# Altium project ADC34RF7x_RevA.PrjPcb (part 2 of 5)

## Sheet ADC34RF7x_ADC_Power_RevA.SchDoc: ADC EVM Power
size 431 x 279 mm; Date: Not shown in title block; ApprovedBy: Not shown in title block; CheckedBy: Not shown in title block; Author: Not shown in title block; CompanyName: Not shown in title block; DrawnBy: CW; Engineer: Not shown in title block; Organization: Not shown in title block; Address1: Not shown in title block; Address2: Not shown in title block; Address3: Not shown in title block; Address4: Not shown in title block; DocumentNumber: 4; Revision: Use project parameter SCH_Rev; SheetNumber: 6; SheetTotal: 20; PageSetup: Record=PageOptions¦CenterHorizontal=True¦CenterVertical=True¦PrintScale=1.00¦XCorrection=1.00¦YCorrection=1.00¦PrintKind=0¦BorderSize=5000000¦LeftOffset=0¦BottomOffset=0¦Orientation=2¦PaperLength=1000¦PaperWidth=1000¦Scale=100¦PaperSource=15¦PrintQuality=600¦MediaType=1¦DitherType=10¦PaperKind=Letter¦PrintScaleMode=1
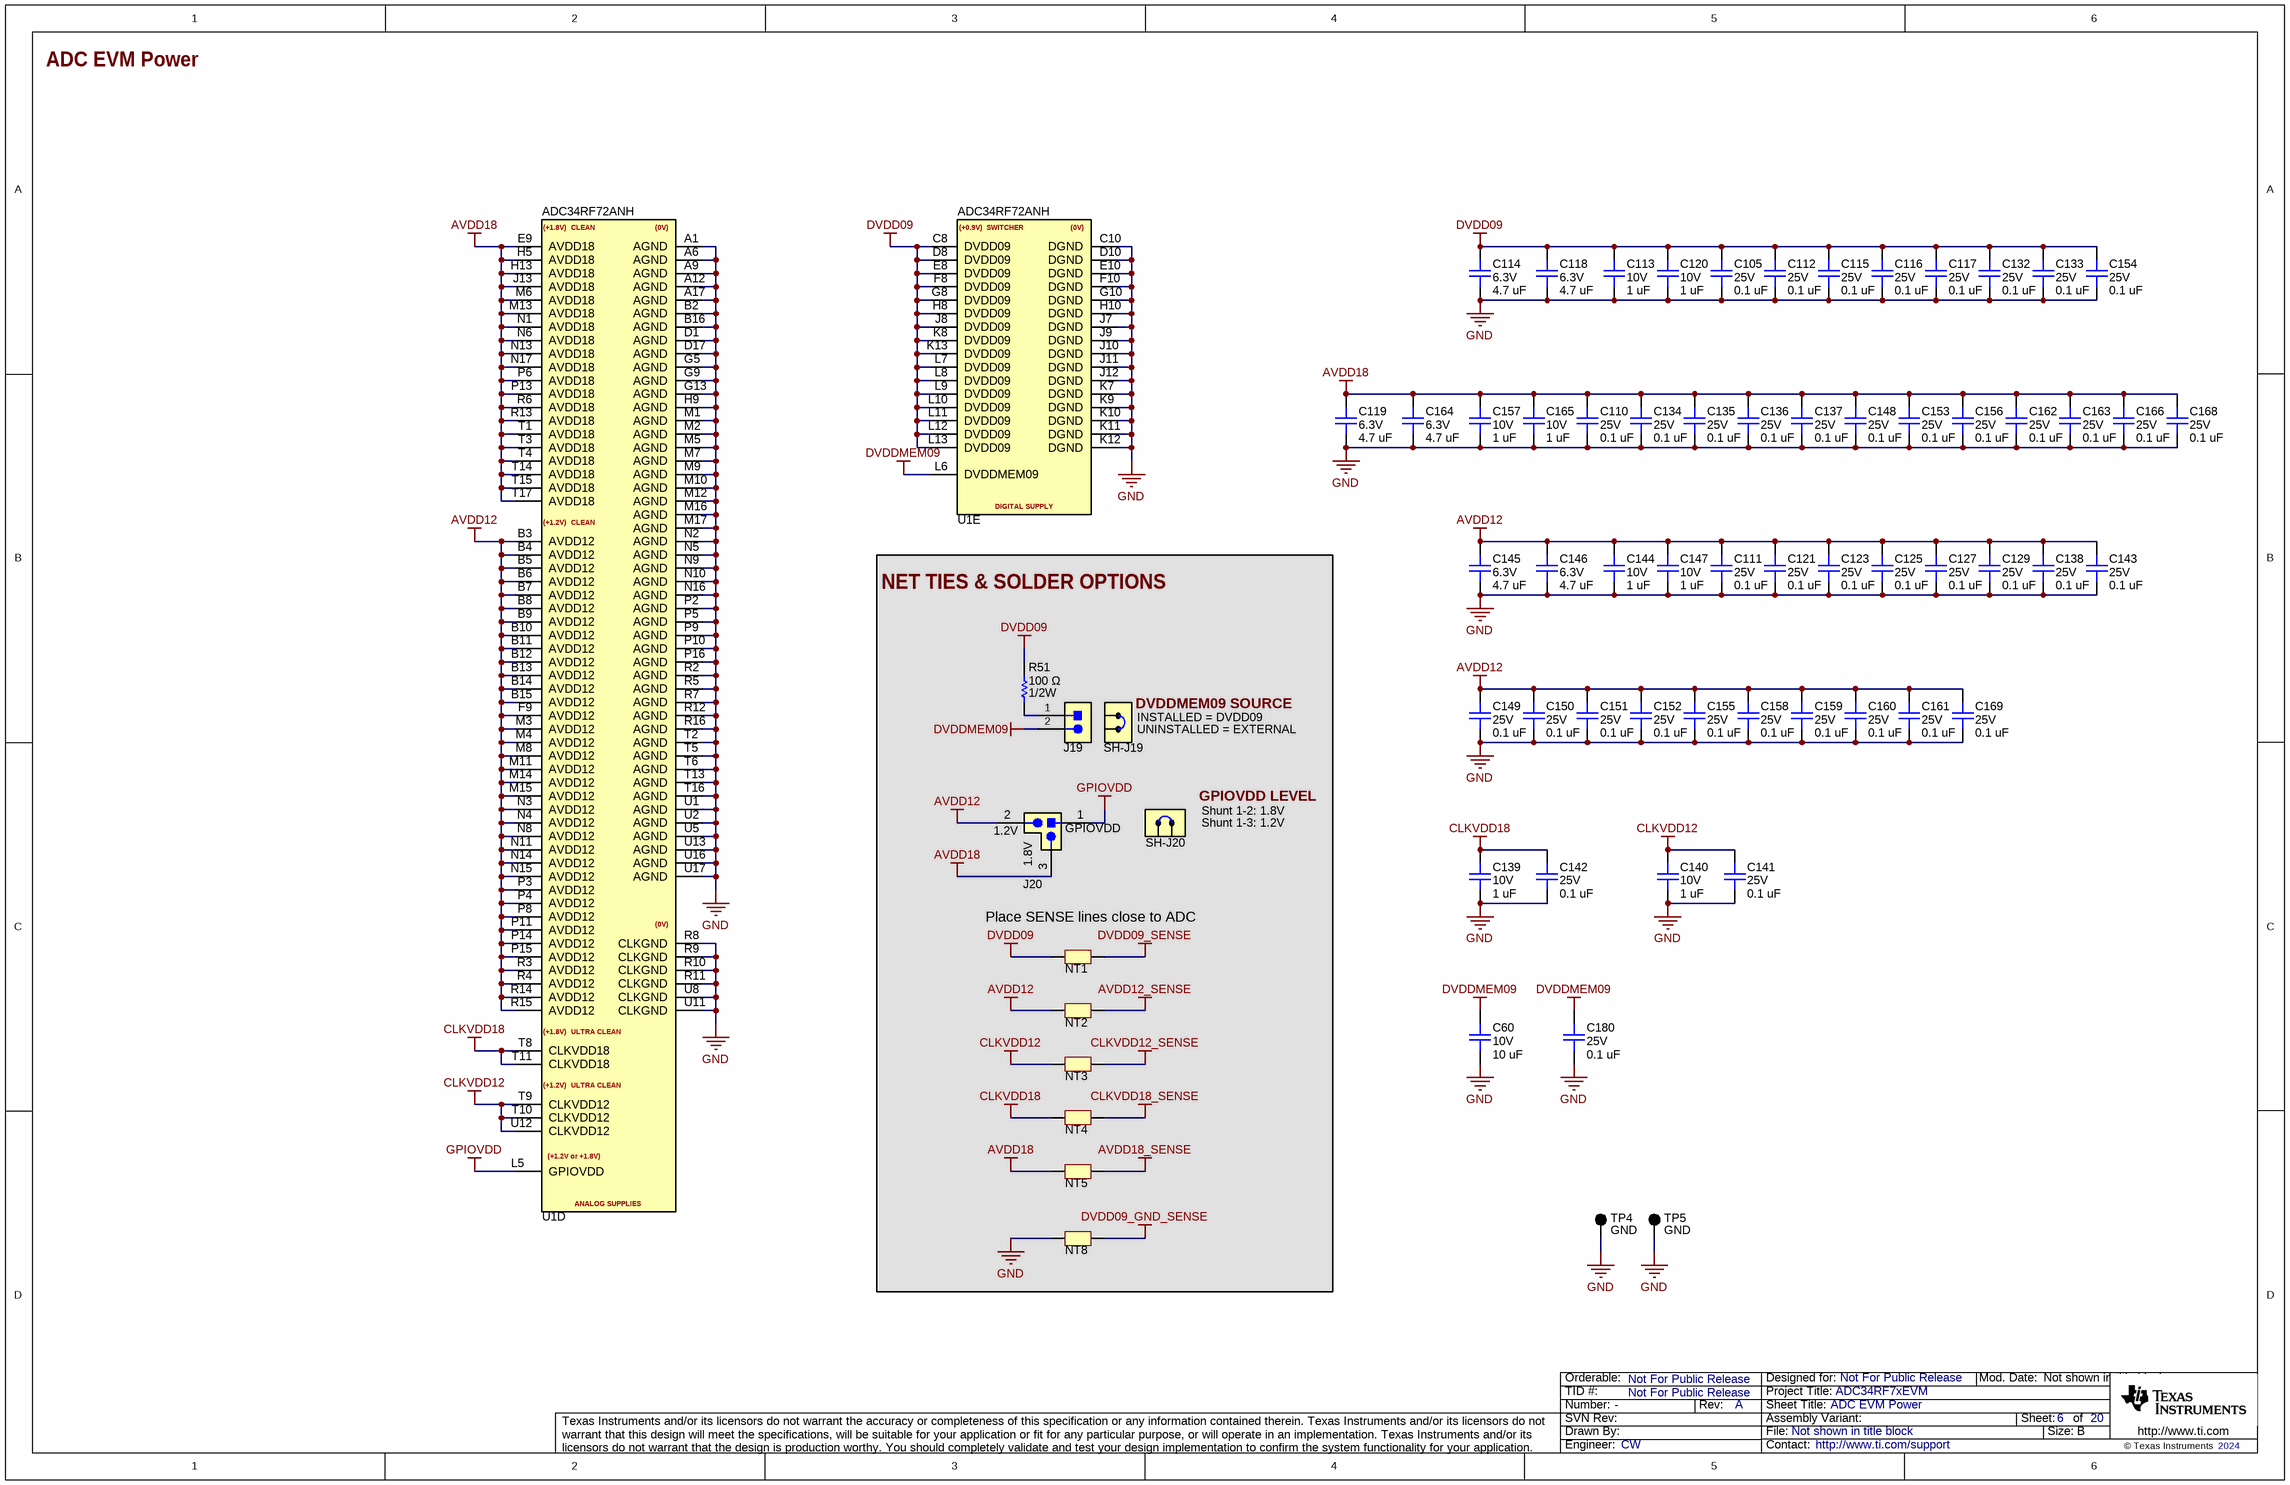
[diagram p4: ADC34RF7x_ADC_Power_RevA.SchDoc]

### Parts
C60  value 10 uF  Voltage - Rated: 10V  [0402L_cap]  (hidden comment: 0402ZD106MAT2A)
C105  value 0.1 uF  Voltage - Rated: 25V  [0201_cap]  (hidden comment: C0603X5R1E104K030BB)
C110  value 0.1 uF  Voltage - Rated: 25V  [0201_cap]  (hidden comment: C0603X5R1E104K030BB)
C111  value 0.1 uF  Voltage - Rated: 25V  [0201_cap]  (hidden comment: C0603X5R1E104K030BB)
C112  value 0.1 uF  Voltage - Rated: 25V  [0201_cap]  (hidden comment: C0603X5R1E104K030BB)
C113  value 1 uF  Voltage - Rated: 10V  [0201_cap]  (hidden comment: GRM033R61A105ME44D)
C114  value 4.7 uF  Voltage - Rated: 6.3V  [0201_cap]  (hidden comment: GRM033R60J475ME05D)
C115  value 0.1 uF  Voltage - Rated: 25V  [0201_cap]  (hidden comment: C0603X5R1E104K030BB)
C116  value 0.1 uF  Voltage - Rated: 25V  [0201_cap]  (hidden comment: C0603X5R1E104K030BB)
C117  value 0.1 uF  Voltage - Rated: 25V  [0201_cap]  (hidden comment: C0603X5R1E104K030BB)
C118  value 4.7 uF  Voltage - Rated: 6.3V  [0201_cap]  (hidden comment: GRM033R60J475ME05D)
C119  value 4.7 uF  Voltage - Rated: 6.3V  [0201_cap]  (hidden comment: GRM033R60J475ME05D)
C120  value 1 uF  Voltage - Rated: 10V  [0201_cap]  (hidden comment: GRM033R61A105ME44D)
C121  value 0.1 uF  Voltage - Rated: 25V  [0201_cap]  (hidden comment: C0603X5R1E104K030BB)
C123  value 0.1 uF  Voltage - Rated: 25V  [0201_cap]  (hidden comment: C0603X5R1E104K030BB)
C125  value 0.1 uF  Voltage - Rated: 25V  [0201_cap]  (hidden comment: C0603X5R1E104K030BB)
C127  value 0.1 uF  Voltage - Rated: 25V  [0201_cap]  (hidden comment: C0603X5R1E104K030BB)
C129  value 0.1 uF  Voltage - Rated: 25V  [0201_cap]  (hidden comment: C0603X5R1E104K030BB)
C132  value 0.1 uF  Voltage - Rated: 25V  [0201_cap]  (hidden comment: C0603X5R1E104K030BB)
C133  value 0.1 uF  Voltage - Rated: 25V  [0201_cap]  (hidden comment: C0603X5R1E104K030BB)
C134  value 0.1 uF  Voltage - Rated: 25V  [0201_cap]  (hidden comment: C0603X5R1E104K030BB)
C135  value 0.1 uF  Voltage - Rated: 25V  [0201_cap]  (hidden comment: C0603X5R1E104K030BB)
C136  value 0.1 uF  Voltage - Rated: 25V  [0201_cap]  (hidden comment: C0603X5R1E104K030BB)
C137  value 0.1 uF  Voltage - Rated: 25V  [0201_cap]  (hidden comment: C0603X5R1E104K030BB)
C138  value 0.1 uF  Voltage - Rated: 25V  [0201_cap]  (hidden comment: C0603X5R1E104K030BB)
C139  value 1 uF  Voltage - Rated: 10V  [0201_cap]  (hidden comment: GRM033R61A105ME44D)
C140  value 1 uF  Voltage - Rated: 10V  [0201_cap]  (hidden comment: GRM033R61A105ME44D)
C141  value 0.1 uF  Voltage - Rated: 25V  [0201_cap]  (hidden comment: C0603X5R1E104K030BB)
C142  value 0.1 uF  Voltage - Rated: 25V  [0201_cap]  (hidden comment: C0603X5R1E104K030BB)
C143  value 0.1 uF  Voltage - Rated: 25V  [0201_cap]  (hidden comment: C0603X5R1E104K030BB)
C144  value 1 uF  Voltage - Rated: 10V  [0201_cap]  (hidden comment: GRM033R61A105ME44D)
C145  value 4.7 uF  Voltage - Rated: 6.3V  [0201_cap]  (hidden comment: GRM033R60J475ME05D)
C146  value 4.7 uF  Voltage - Rated: 6.3V  [0201_cap]  (hidden comment: GRM033R60J475ME05D)
C147  value 1 uF  Voltage - Rated: 10V  [0201_cap]  (hidden comment: GRM033R61A105ME44D)
C148  value 0.1 uF  Voltage - Rated: 25V  [0201_cap]  (hidden comment: C0603X5R1E104K030BB)
C149  value 0.1 uF  Voltage - Rated: 25V  [0201_cap]  (hidden comment: C0603X5R1E104K030BB)
C150  value 0.1 uF  Voltage - Rated: 25V  [0201_cap]  (hidden comment: C0603X5R1E104K030BB)
C151  value 0.1 uF  Voltage - Rated: 25V  [0201_cap]  (hidden comment: C0603X5R1E104K030BB)
C152  value 0.1 uF  Voltage - Rated: 25V  [0201_cap]  (hidden comment: C0603X5R1E104K030BB)
C153  value 0.1 uF  Voltage - Rated: 25V  [0201_cap]  (hidden comment: C0603X5R1E104K030BB)
C154  value 0.1 uF  Voltage - Rated: 25V  [0201_cap]  (hidden comment: C0603X5R1E104K030BB)
C155  value 0.1 uF  Voltage - Rated: 25V  [0201_cap]  (hidden comment: C0603X5R1E104K030BB)
C156  value 0.1 uF  Voltage - Rated: 25V  [0201_cap]  (hidden comment: C0603X5R1E104K030BB)
C157  value 1 uF  Voltage - Rated: 10V  [0201_cap]  (hidden comment: GRM033R61A105ME44D)
C158  value 0.1 uF  Voltage - Rated: 25V  [0201_cap]  (hidden comment: C0603X5R1E104K030BB)
C159  value 0.1 uF  Voltage - Rated: 25V  [0201_cap]  (hidden comment: C0603X5R1E104K030BB)
C160  value 0.1 uF  Voltage - Rated: 25V  [0201_cap]  (hidden comment: C0603X5R1E104K030BB)
C161  value 0.1 uF  Voltage - Rated: 25V  [0201_cap]  (hidden comment: C0603X5R1E104K030BB)
C162  value 0.1 uF  Voltage - Rated: 25V  [0201_cap]  (hidden comment: C0603X5R1E104K030BB)
C163  value 0.1 uF  Voltage - Rated: 25V  [0201_cap]  (hidden comment: C0603X5R1E104K030BB)
C164  value 4.7 uF  Voltage - Rated: 6.3V  [0201_cap]  (hidden comment: GRM033R60J475ME05D)
C165  value 1 uF  Voltage - Rated: 10V  [0201_cap]  (hidden comment: GRM033R61A105ME44D)
C166  value 0.1 uF  Voltage - Rated: 25V  [0201_cap]  (hidden comment: C0603X5R1E104K030BB)
C168  value 0.1 uF  Voltage - Rated: 25V  [0201_cap]  (hidden comment: C0603X5R1E104K030BB)
C169  value 0.1 uF  Voltage - Rated: 25V  [0201_cap]  (hidden comment: C0603X5R1E104K030BB)
C180  value 0.1 uF  Voltage - Rated: 25V  [0201_cap]  (hidden comment: C0603X5R1E104K030BB)
J19  GRPB021VWVN-RC  [PBC02SAAN]  (value not drawn)
J20  Text3: 1.8V  Text2: 1.2V  Text1: GPIOVDD  [l-header]  (hidden comment: L-Header)
NT1  Net-Tie  [Net-Tie_6x8mil]  (value not drawn)  (net tie, no BOM)
NT2  Net-Tie  [Net-Tie_6x8mil]  (value not drawn)  (net tie, no BOM)
NT3  Net-Tie  [Net-Tie_6x8mil]  (value not drawn)  (net tie, no BOM)
NT4  Net-Tie  [Net-Tie_6x8mil]  (value not drawn)  (net tie, no BOM)
NT5  Net-Tie  [Net-Tie_6x8mil]  (value not drawn)  (net tie, no BOM)
NT8  Net-Tie  [Net-Tie_6x8mil]  (value not drawn)  (net tie, no BOM)
R51  value 100 Ω  Power (Watts): 1/2W  [0805L]  (hidden comment: ERJ-HP6F1000V)
SH-J19  SPC02SYAN  [SPC02SYAN]  (value not drawn)
SH-J20  SPC02SYAN  [SPC02SYAN]  (value not drawn)
TP4  Text1: GND  [Keystone5001]  (hidden comment: 5001)
TP5  Text1: GND  [Keystone5001]  (hidden comment: 5001)
U1  ADC34RF72ANH  [ANH0289A]  (parts D,E of 8)

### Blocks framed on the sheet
NET TIES & SOLDER OPTIONS: J19 J20 NT1-NT5 NT8 R51 SH-J19 SH-J20

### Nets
AVDD12: C111.2 C121.2 C123.2 C125.2 C127.2 C129.2 C138.2 C143.2 C144.2 C145.2 C146.2 C147.2 C149.2 C150.2 C151.2 C152.2 C155.2 C158.2 C159.2 C160.2 C161.2 C169.2 J20.2 NT2.2 U1.B3(AVDD12) U1.B4(AVDD12) U1.B5(AVDD12) U1.B6(AVDD12) U1.B7(AVDD12) U1.B8(AVDD12) U1.B9(AVDD12) U1.B10(AVDD12) U1.B11(AVDD12) U1.B12(AVDD12) U1.B13(AVDD12) U1.B14(AVDD12) U1.B15(AVDD12) U1.F9(AVDD12) U1.M3(AVDD12) U1.M4(AVDD12) U1.M8(AVDD12) U1.M11(AVDD12) U1.M14(AVDD12) U1.M15(AVDD12) U1.N3(AVDD12) U1.N4(AVDD12) U1.N8(AVDD12) U1.N11(AVDD12) U1.N14(AVDD12) U1.N15(AVDD12) U1.P3(AVDD12) U1.P4(AVDD12) U1.P8(AVDD12) U1.P11(AVDD12) U1.P14(AVDD12) U1.P15(AVDD12) U1.R3(AVDD12) U1.R4(AVDD12) U1.R14(AVDD12) U1.R15(AVDD12)
AVDD12_SENSE: NT2.1
AVDD18: C110.2 C119.2 C134.2 C135.2 C136.2 C137.2 C148.2 C153.2 C156.2 C157.2 C162.2 C163.2 C164.2 C165.2 C166.2 C168.2 J20.3 NT5.2 U1.E9(AVDD18) U1.H5(AVDD18) U1.H13(AVDD18) U1.J13(AVDD18) U1.M6(AVDD18) U1.M13(AVDD18) U1.N1(AVDD18) U1.N6(AVDD18) U1.N13(AVDD18) U1.N17(AVDD18) U1.P6(AVDD18) U1.P13(AVDD18) U1.R6(AVDD18) U1.R13(AVDD18) U1.T1(AVDD18) U1.T3(AVDD18) U1.T4(AVDD18) U1.T14(AVDD18) U1.T15(AVDD18) U1.T17(AVDD18)
AVDD18_SENSE: NT5.1
CLKVDD12: C140.2 C141.2 NT3.2 U1.T9(CLKVDD12) U1.T10(CLKVDD12) U1.U12(CLKVDD12)
CLKVDD12_SENSE: NT3.1
CLKVDD18: C139.2 C142.2 NT4.2 U1.T8(CLKVDD18) U1.T11(CLKVDD18)
CLKVDD18_SENSE: NT4.1
DVDD09: C105.2 C112.2 C113.2 C114.2 C115.2 C116.2 C117.2 C118.2 C120.2 C132.2 C133.2 C154.2 NT1.2 R51.2 U1.C8(DVDD09) U1.D8(DVDD09) U1.E8(DVDD09) U1.F8(DVDD09) U1.G8(DVDD09) U1.H8(DVDD09) U1.J8(DVDD09) U1.K8(DVDD09) U1.K13(DVDD09) U1.L7(DVDD09) U1.L8(DVDD09) U1.L9(DVDD09) U1.L10(DVDD09) U1.L11(DVDD09) U1.L12(DVDD09) U1.L13(DVDD09)
DVDD09_GND_SENSE: NT8.1
DVDD09_SENSE: NT1.1
DVDDMEM09: C60.2 C180.2 J19.2 U1.L6(DVDDMEM09)
GND: C60.1 C105.1 C110.1 C111.1 C112.1 C113.1 C114.1 C115.1 C116.1 C117.1 C118.1 C119.1 C120.1 C121.1 C123.1 C125.1 C127.1 C129.1 C132.1 C133.1 C134.1 C135.1 C136.1 C137.1 C138.1 C139.1 C140.1 C141.1 C142.1 C143.1 C144.1 C145.1 C146.1 C147.1 C148.1 C149.1 C150.1 C151.1 C152.1 C153.1 C154.1 C155.1 C156.1 C157.1 C158.1 C159.1 C160.1 C161.1 C162.1 C163.1 C164.1 C165.1 C166.1 C168.1 C169.1 C180.1 NT8.2 TP4.1 TP5.1 U1.A1(AGND) U1.A6(AGND) U1.A9(AGND) U1.A12(AGND) U1.A17(AGND) U1.B2(AGND) U1.B16(AGND) U1.C10(DGND) U1.D1(AGND) U1.D10(DGND) U1.D17(AGND) U1.E10(DGND) U1.F10(DGND) U1.G5(AGND) U1.G9(AGND) U1.G10(DGND) U1.G13(AGND) U1.H9(AGND) U1.H10(DGND) U1.J7(DGND) U1.J9(DGND) U1.J10(DGND) U1.J11(DGND) U1.J12(DGND) U1.K7(DGND) U1.K9(DGND) U1.K10(DGND) U1.K11(DGND) U1.K12(DGND) U1.M1(AGND) U1.M2(AGND) U1.M5(AGND) U1.M7(AGND) U1.M9(AGND) U1.M10(AGND) U1.M12(AGND) U1.M16(AGND) U1.M17(AGND) U1.N2(AGND) U1.N5(AGND) U1.N9(AGND) U1.N10(AGND) U1.N16(AGND) U1.P2(AGND) U1.P5(AGND) U1.P9(AGND) U1.P10(AGND) U1.P16(AGND) U1.R2(AGND) U1.R5(AGND) U1.R7(AGND) U1.R8(CLKGND) U1.R9(CLKGND) U1.R10(CLKGND) U1.R11(CLKGND) U1.R12(AGND) U1.R16(AGND) U1.T2(AGND) U1.T5(AGND) U1.T6(AGND) U1.T13(AGND) U1.T16(AGND) U1.U1(AGND) U1.U2(AGND) U1.U5(AGND) U1.U8(CLKGND) U1.U11(CLKGND) U1.U13(AGND) U1.U16(AGND) U1.U17(AGND)
GPIOVDD: J20.1 U1.L5(GPIOVDD)
NetJ19_1: J19.1 R51.1

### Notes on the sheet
- (near SH-J19) DVDDMEM09 SOURCE
- (near SH-J19) INSTALLED = DVDD09
- (near SH-J19) UNINSTALLED = EXTERNAL
- (near SH-J20) GPIOVDD LEVEL
- (near SH-J20) Shunt 1-2: 1.8V
- (near SH-J20) Shunt 1-3: 1.2V
- (near NT1) Place SENSE lines close to ADC

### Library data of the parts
C60 = capcc09406: CAP CER 10UF 10V X5R 0402; Manufacturer: KYOCERA AVX; CompType: Capacitor Ceramic; Tolerance: ±20%; SizeX_mm: 1; SizeY_mm: 0.5; SizeZ_mm: 0.7
C105 C110-C112 C115-C117 C121 C123 C125 C127 C129 C132-C138 C141-C143 C148-C156 C158-C163 C166 C168 C169 C180 = capcc01294: CAP CER 0.1UF 25V X5R 0201; Manufacturer: TDK Corporation; CompType: Capacitor Ceramic; Tolerance: ±10%; SizeX_mm: 0.6; SizeY_mm: 0.3; SizeZ_mm: 0.33
C113 C120 C139 C140 C144 C147 C157 C165 = capcc09264: CAP CER 1UF 10V X5R 0201; Manufacturer: Murata Electronics; CompType: Capacitor Ceramic; Tolerance: ±20%; SizeX_mm: 0.6; SizeY_mm: 0.3; SizeZ_mm: 0.33
C114 C118 C119 C145 C146 C164 = capcc09251: CAP CER 4.7UF 6.3V X5R 0201; Manufacturer: Murata Electronics; CompType: Capacitor Ceramic; Tolerance: ±20%; SizeX_mm: 0.6; SizeY_mm: 0.3; SizeZ_mm: 0.33
J19 = TSW-102-14-L-S: Header, 100mil, 2x1, Gold, TH; Manufacturer: Samtec; Alt Manufacturer: Sullins Connector Solutions; UniqueID: cmp00014; Pitch (mm): 2.54
J20 = L-Header: "L" Configuration Headers Connector Header Through Hole 3 position 100mils; UniqueID: cmp00511; CompType: Wire Housing
NT1-NT5 NT8 = CMP-0078142-6: Single point connection between nets.
R51 = RSMD080507476: RES 100 OHM 1% 1/2W 0805; Manufacturer: Panasonic Electronic Components; CompType: Resistor SMD; Temperature Coefficient: ±100ppm/°C; SizeX_mm: 2; SizeY_mm: 1.25; SizeZ_mm: 0.7
SH-J19 SH-J20 = cmp00093: 2 (1 x 2) Position Shunt Connector Black Closed Top 0.100" (2.54mm) Gold; Manufacturer: Sullins; Value: 1x2; Note: You can "mate" this to a header by matching the designator.  i.e. use SH-J3 for header J3; Pitch (mm): 2.54
TP4 TP5 = cmp00051: Test Point, Miniature, Black TH; Manufacturer: Keystone
U1 = ADC34RF72ANH: Quad channel 16-bit 1.5 GSPS RF sampling data converter, FCCSP-289 (ANH0289A); Alternate Manufacturer: Texas Instruments; SizeX_mm: 14; CompType: IC; SizeZ_mm: 1.9; SizeArea_mm2: 196; AEC Qualified: N

## Sheet ADC34RF7x_FMC_RevA.SchDoc: FMC Connector
size 431 x 279 mm; Date: Not shown in title block; ApprovedBy: Not shown in title block; CheckedBy: Not shown in title block; Author: Not shown in title block; CompanyName: Not shown in title block; DrawnBy: CW; Engineer: Not shown in title block; Organization: Not shown in title block; Address1: Not shown in title block; Address2: Not shown in title block; Address3: Not shown in title block; Address4: Not shown in title block; DocumentNumber: 5; Revision: Use project parameter SCH_Rev; SheetNumber: 7; SheetTotal: 19; PageSetup: Record=PageOptions¦CenterHorizontal=True¦CenterVertical=True¦PrintScale=1.00¦XCorrection=1.00¦YCorrection=1.00¦PrintKind=0¦BorderSize=5000000¦LeftOffset=0¦BottomOffset=0¦Orientation=2¦PaperLength=1000¦PaperWidth=1000¦Scale=100¦PaperSource=15¦PrintQuality=600¦MediaType=1¦DitherType=10¦PaperKind=Letter¦PrintScaleMode=1
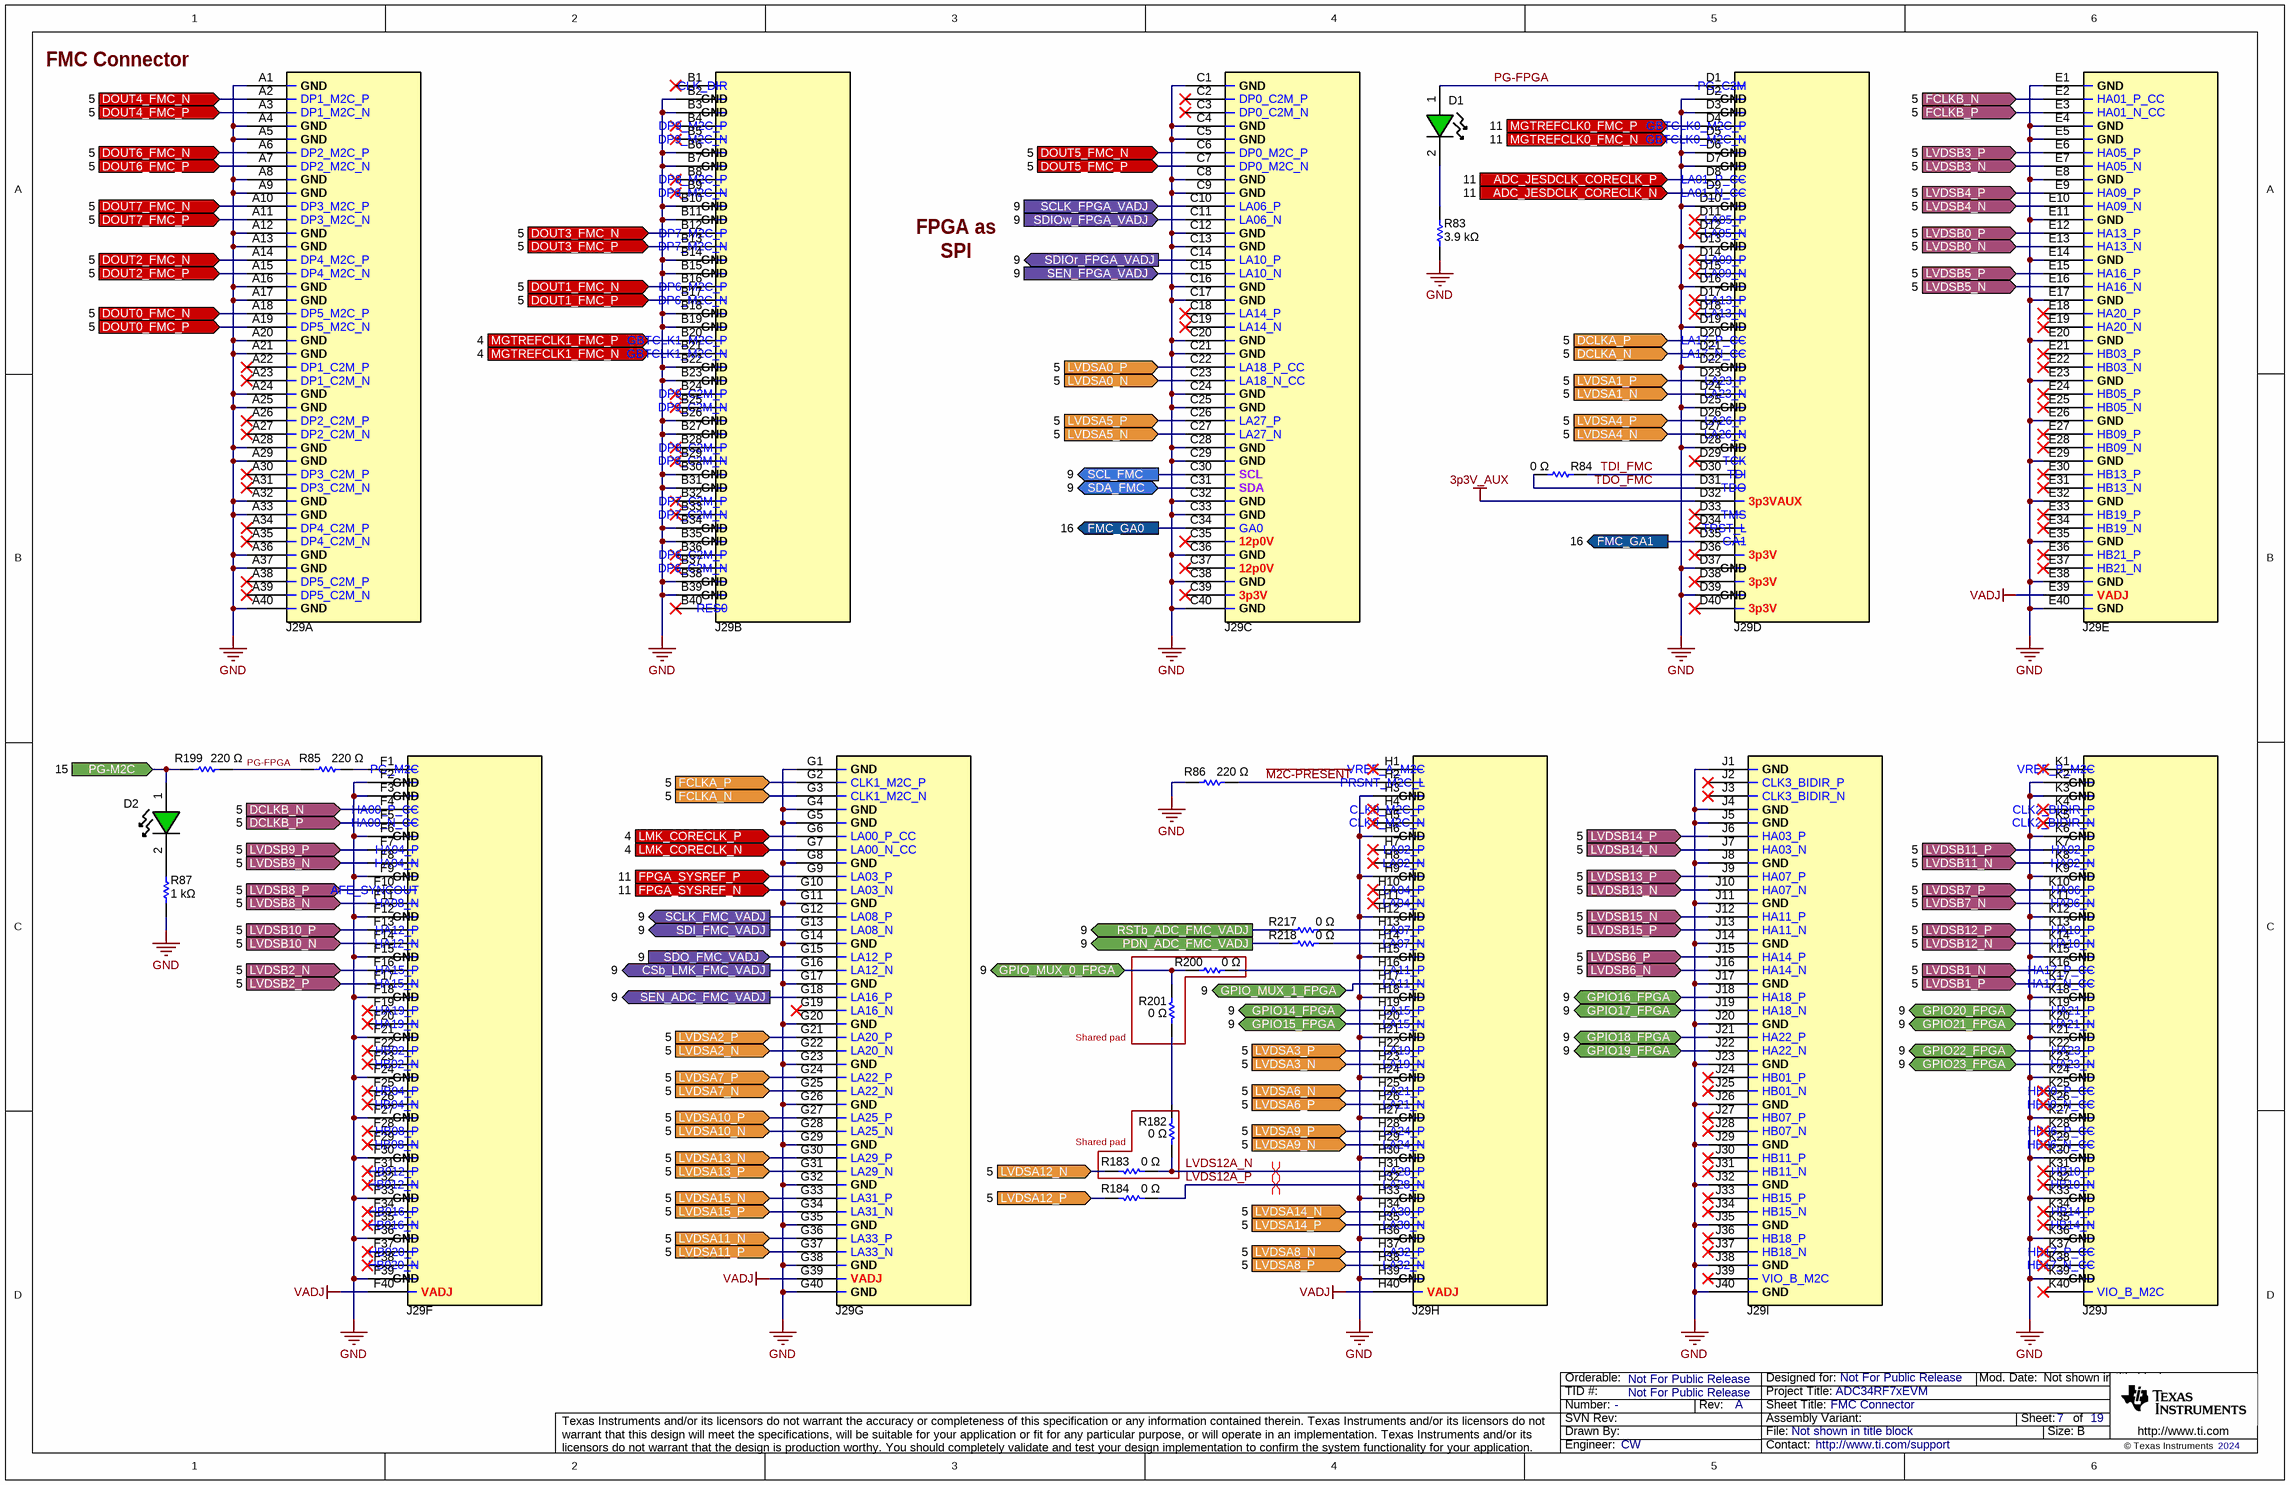
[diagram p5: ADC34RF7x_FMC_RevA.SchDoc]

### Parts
D1  LTST-C191TGKT  [LED_LTST-C190-Green]  (value not drawn)
D2  LTST-C191TGKT  [LED_LTST-C190-Green]  (value not drawn)
J29  ASP-134488-01  [SAMTEC_ASP-134488-01]  (value not drawn)  (parts A,B,C,D,E,F,G,H,I,J of 10)
R83  value 3.9 kΩ  [0402L]  (hidden comment: ERJ-H2GJ392X)
R84  value 0 Ω  [0201]  (hidden comment: ERJ-1GN0R00C)
R85  value 220 Ω  [0201]  (hidden comment: ERJ-1GNF2200C)
R86  value 220 Ω  [0201]  (hidden comment: ERJ-1GNF2200C)
R87  value 1 kΩ  [0402L]  (hidden comment: ERJ-PA2F1001X)
R182  value 0 Ω  [0201]  (hidden comment: ERJ-1GN0R00C)
R183  value 0 Ω  [0201]  (hidden comment: ERJ-1GN0R00C)
R184  value 0 Ω  [0201]  (hidden comment: ERJ-1GN0R00C)
R199  value 220 Ω  [0201]  (hidden comment: ERJ-1GNF2200C)
R200  value 0 Ω  [0201]  (hidden comment: ERJ-1GN0R00C)
R201  value 0 Ω  [0201]  (hidden comment: ERJ-1GN0R00C)
R217  value 0 Ω  [0201]  (hidden comment: ERJ-1GN0R00C)
R218  value 0 Ω  [0201]  (hidden comment: ERJ-1GN0R00C)

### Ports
ADC_JESDCLK_CORECLK_N (in, see 11), ADC_JESDCLK_CORECLK_P (in, see 11), CSb_LMK_FMC_VADJ (out, see 9), DCLKA_N (in, see 5), DCLKA_P (in, see 5), DCLKB_N (in, see 5), DCLKB_P (in, see 5), DOUT0_FMC_N (in, see 5), DOUT0_FMC_P (in, see 5), DOUT1_FMC_N (in, see 5), DOUT1_FMC_P (in, see 5), DOUT2_FMC_N (in, see 5), DOUT2_FMC_P (in, see 5), DOUT3_FMC_N (in, see 5), DOUT3_FMC_P (in, see 5), DOUT4_FMC_N (in, see 5), DOUT4_FMC_P (in, see 5), DOUT5_FMC_N (in, see 5), DOUT5_FMC_P (in, see 5), DOUT6_FMC_N (in, see 5), DOUT6_FMC_P (in, see 5), DOUT7_FMC_N (in, see 5), DOUT7_FMC_P (in, see 5), FCLKA_N (in, see 5), FCLKA_P (in, see 5), FCLKB_N (in, see 5), FCLKB_P (in, see 5), FMC_GA0 (out, see 16), FMC_GA1 (out, see 16), FPGA_SYSREF_N (in, see 11), FPGA_SYSREF_P (in, see 11), GPIO14_FPGA (bidir, see 9), GPIO15_FPGA (bidir, see 9), GPIO16_FPGA (bidir, see 9), GPIO17_FPGA (bidir, see 9), GPIO18_FPGA (bidir, see 9), GPIO19_FPGA (bidir, see 9), GPIO20_FPGA (bidir, see 9), GPIO21_FPGA (bidir, see 9), GPIO22_FPGA (bidir, see 9), GPIO23_FPGA (bidir, see 9), GPIO_MUX_0_FPGA (bidir, see 9), GPIO_MUX_1_FPGA (bidir, see 9), LMK_CORECLK_N (in, see 4), LMK_CORECLK_P (in, see 4), LVDSA0_N (in, see 5), LVDSA0_P (in, see 5), LVDSA1_N (in, see 5), LVDSA1_P (in, see 5), LVDSA2_N (in, see 5), LVDSA2_P (in, see 5), LVDSA3_N (in, see 5), LVDSA3_P (in, see 5), LVDSA4_N (in, see 5), LVDSA4_P (in, see 5), LVDSA5_N (in, see 5), LVDSA5_P (in, see 5), LVDSA6_N (in, see 5), LVDSA6_P (in, see 5), LVDSA7_N (in, see 5), LVDSA7_P (in, see 5), LVDSA8_N (in, see 5), LVDSA8_P (in, see 5), LVDSA9_N (in, see 5), LVDSA9_P (in, see 5), LVDSA10_N (in, see 5), LVDSA10_P (in, see 5), LVDSA11_N (in, see 5), LVDSA11_P (in, see 5), LVDSA12_N (in, see 5), LVDSA12_P (in, see 5), LVDSA13_N (in, see 5), LVDSA13_P (in, see 5), LVDSA14_N (in, see 5), LVDSA14_P (in, see 5), LVDSA15_N (in, see 5), LVDSA15_P (in, see 5), LVDSB0_N (in, see 5), LVDSB0_P (in, see 5), LVDSB1_N (in, see 5), LVDSB1_P (in, see 5), LVDSB2_N (in, see 5), LVDSB2_P (in, see 5), LVDSB3_N (in, see 5), LVDSB3_P (in, see 5), LVDSB4_N (in, see 5), LVDSB4_P (in, see 5), LVDSB5_N (in, see 5), LVDSB5_P (in, see 5), LVDSB6_N (in, see 5), LVDSB6_P (in, see 5), LVDSB7_N (in, see 5), LVDSB7_P (in, see 5), LVDSB8_N (in, see 5), LVDSB8_P (in, see 5), LVDSB9_N (in, see 5), LVDSB9_P (in, see 5), LVDSB10_N (in, see 5), LVDSB10_P (in, see 5), LVDSB11_N (in, see 5), LVDSB11_P (in, see 5), LVDSB12_N (in, see 5), LVDSB12_P (in, see 5), LVDSB13_N (in, see 5), LVDSB13_P (in, see 5), LVDSB14_N (in, see 5), LVDSB14_P (in, see 5), LVDSB15_N (in, see 5), LVDSB15_P (in, see 5), MGTREFCLK0_FMC_N (in, see 11), MGTREFCLK0_FMC_P (in, see 11), MGTREFCLK1_FMC_N (in, see 4), MGTREFCLK1_FMC_P (in, see 4), PDN_ADC_FMC_VADJ (out, see 9), PG-M2C (in, see 15), RSTb_ADC_FMC_VADJ (out, see 9), SCL_FMC (out, see 9), SCLK_FMC_VADJ (out, see 9), SCLK_FPGA_VADJ (in, see 9), SDA_FMC (bidir, see 9), SDI_FMC_VADJ (out, see 9), SDIOr_FPGA_VADJ (out, see 9), SDIOw_FPGA_VADJ (in, see 9), SDO_FMC_VADJ (in, see 9), SEN_ADC_FMC_VADJ (out, see 9), SEN_FPGA_VADJ (in, see 9)

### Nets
3p3V_AUX: J29.D32
GND: J29.A1 J29.A4 J29.A5 J29.A8 J29.A9 J29.A12 J29.A13 J29.A16 J29.A17 J29.A20 J29.A21 J29.A24 J29.A25 J29.A28 J29.A29 J29.A32 J29.A33 J29.A36 J29.A37 J29.A40 J29.B2 J29.B3 J29.B6 J29.B7 J29.B10 J29.B11 J29.B14 J29.B15 J29.B18 J29.B19 J29.B22 J29.B23 J29.B26 J29.B27 J29.B30 J29.B31 J29.B34 J29.B35 J29.B38 J29.B39 J29.C1 J29.C4 J29.C5 J29.C8 J29.C9 J29.C12 J29.C13 J29.C16 J29.C17 J29.C20 J29.C21 J29.C24 J29.C25 J29.C28 J29.C29 J29.C32 J29.C33 J29.C36 J29.C38 J29.C40 J29.D2 J29.D3 J29.D6 J29.D7 J29.D10 J29.D13 J29.D16 J29.D19 J29.D22 J29.D25 J29.D28 J29.D37 J29.D39 J29.E1 J29.E4 J29.E5 J29.E8 J29.E11 J29.E14 J29.E17 J29.E20 J29.E23 J29.E26 J29.E29 J29.E32 J29.E35 J29.E38 J29.E40 J29.F2 J29.F3 J29.F6 J29.F9 J29.F12 J29.F15 J29.F18 J29.F21 J29.F24 J29.F27 J29.F30 J29.F33 J29.F36 J29.F39 J29.G1 J29.G4 J29.G5 J29.G8 J29.G11 J29.G14 J29.G17 J29.G20 J29.G23 J29.G26 J29.G29 J29.G32 J29.G35 J29.G38 J29.G40 J29.H3 J29.H6 J29.H9 J29.H12 J29.H15 J29.H18 J29.H21 J29.H24 J29.H27 J29.H30 J29.H33 J29.H36 J29.H39 J29.J1 J29.J4 J29.J5 J29.J8 J29.J11 J29.J14 J29.J17 J29.J20 J29.J23 J29.J26 J29.J29 J29.J32 J29.J35 J29.J38 J29.J40 J29.K2 J29.K3 J29.K6 J29.K9 J29.K12 J29.K15 J29.K18 J29.K21 J29.K24 J29.K27 J29.K30 J29.K33 J29.K36 J29.K39 R83.1 R86.1 R87.1
VADJ: J29.E39 J29.F40 J29.G39 J29.H40
~{M2C-PRESENT}: J29.H2 R86.2
ADC_JESDCLK_CORECLK_N: J29.D9 ; port ADC_JESDCLK_CORECLK_N
ADC_JESDCLK_CORECLK_P: J29.D8 ; port ADC_JESDCLK_CORECLK_P
CSb_LMK_FMC_VADJ: J29.G16 ; port CSb_LMK_FMC_VADJ
DCLKA_N: J29.D21 ; port DCLKA_N
DCLKA_P: J29.D20 ; port DCLKA_P
DCLKB_N: J29.F4 ; port DCLKB_N
DCLKB_P: J29.F5 ; port DCLKB_P
DOUT0_FMC_N: J29.A18 ; port DOUT0_FMC_N
DOUT0_FMC_P: J29.A19 ; port DOUT0_FMC_P
DOUT1_FMC_N: J29.B16 ; port DOUT1_FMC_N
DOUT1_FMC_P: J29.B17 ; port DOUT1_FMC_P
DOUT2_FMC_N: J29.A14 ; port DOUT2_FMC_N
DOUT2_FMC_P: J29.A15 ; port DOUT2_FMC_P
DOUT3_FMC_N: J29.B12 ; port DOUT3_FMC_N
DOUT3_FMC_P: J29.B13 ; port DOUT3_FMC_P
DOUT4_FMC_N: J29.A2 ; port DOUT4_FMC_N
DOUT4_FMC_P: J29.A3 ; port DOUT4_FMC_P
DOUT5_FMC_N: J29.C6 ; port DOUT5_FMC_N
DOUT5_FMC_P: J29.C7 ; port DOUT5_FMC_P
DOUT6_FMC_N: J29.A6 ; port DOUT6_FMC_N
DOUT6_FMC_P: J29.A7 ; port DOUT6_FMC_P
DOUT7_FMC_N: J29.A10 ; port DOUT7_FMC_N
DOUT7_FMC_P: J29.A11 ; port DOUT7_FMC_P
FCLKA_N: J29.G3 ; port FCLKA_N
FCLKA_P: J29.G2 ; port FCLKA_P
FCLKB_N: J29.E2 ; port FCLKB_N
FCLKB_P: J29.E3 ; port FCLKB_P
FMC_GA0: J29.C34 ; port FMC_GA0
FMC_GA1: J29.D35 ; port FMC_GA1
FPGA_SYSREF_N: J29.G10 ; port FPGA_SYSREF_N
FPGA_SYSREF_P: J29.G9 ; port FPGA_SYSREF_P
GPIO14_FPGA: J29.H19 ; port GPIO14_FPGA
GPIO15_FPGA: J29.H20 ; port GPIO15_FPGA
GPIO16_FPGA: J29.J18 ; port GPIO16_FPGA
GPIO17_FPGA: J29.J19 ; port GPIO17_FPGA
GPIO18_FPGA: J29.J21 ; port GPIO18_FPGA
GPIO19_FPGA: J29.J22 ; port GPIO19_FPGA
GPIO20_FPGA: J29.K19 ; port GPIO20_FPGA
GPIO21_FPGA: J29.K20 ; port GPIO21_FPGA
GPIO22_FPGA: J29.K22 ; port GPIO22_FPGA
GPIO23_FPGA: J29.K23 ; port GPIO23_FPGA
GPIO_MUX_0_FPGA: R200.1 R201.2 ; port GPIO_MUX_0_FPGA
GPIO_MUX_1_FPGA: J29.H17 ; port GPIO_MUX_1_FPGA
LMK_CORECLK_N: J29.G7 ; port LMK_CORECLK_N
LMK_CORECLK_P: J29.G6 ; port LMK_CORECLK_P
LVDS12A_N: J29.H31 R182.1 R183.1
LVDS12A_P: J29.H32 R184.1
LVDSA0_N: J29.C23 ; port LVDSA0_N
LVDSA0_P: J29.C22 ; port LVDSA0_P
LVDSA1_N: J29.D24 ; port LVDSA1_N
LVDSA1_P: J29.D23 ; port LVDSA1_P
LVDSA2_N: J29.G22 ; port LVDSA2_N
LVDSA2_P: J29.G21 ; port LVDSA2_P
LVDSA3_N: J29.H23 ; port LVDSA3_N
LVDSA3_P: J29.H22 ; port LVDSA3_P
LVDSA4_N: J29.D27 ; port LVDSA4_N
LVDSA4_P: J29.D26 ; port LVDSA4_P
LVDSA5_N: J29.C27 ; port LVDSA5_N
LVDSA5_P: J29.C26 ; port LVDSA5_P
LVDSA6_N: J29.H25 ; port LVDSA6_N
LVDSA6_P: J29.H26 ; port LVDSA6_P
LVDSA7_N: J29.G25 ; port LVDSA7_N
LVDSA7_P: J29.G24 ; port LVDSA7_P
LVDSA8_N: J29.H37 ; port LVDSA8_N
LVDSA8_P: J29.H38 ; port LVDSA8_P
LVDSA9_N: J29.H29 ; port LVDSA9_N
LVDSA9_P: J29.H28 ; port LVDSA9_P
LVDSA10_N: J29.G28 ; port LVDSA10_N
LVDSA10_P: J29.G27 ; port LVDSA10_P
LVDSA11_N: J29.G36 ; port LVDSA11_N
LVDSA11_P: J29.G37 ; port LVDSA11_P
LVDSA12_N: R183.2 ; port LVDSA12_N
LVDSA12_P: R184.2 ; port LVDSA12_P
LVDSA13_N: J29.G30 ; port LVDSA13_N
LVDSA13_P: J29.G31 ; port LVDSA13_P
LVDSA14_N: J29.H34 ; port LVDSA14_N
LVDSA14_P: J29.H35 ; port LVDSA14_P
LVDSA15_N: J29.G33 ; port LVDSA15_N
LVDSA15_P: J29.G34 ; port LVDSA15_P
LVDSB0_N: J29.E13 ; port LVDSB0_N
LVDSB0_P: J29.E12 ; port LVDSB0_P
LVDSB1_N: J29.K16 ; port LVDSB1_N
LVDSB1_P: J29.K17 ; port LVDSB1_P
LVDSB2_N: J29.F16 ; port LVDSB2_N
LVDSB2_P: J29.F17 ; port LVDSB2_P
LVDSB3_N: J29.E7 ; port LVDSB3_N
LVDSB3_P: J29.E6 ; port LVDSB3_P
LVDSB4_N: J29.E10 ; port LVDSB4_N
LVDSB4_P: J29.E9 ; port LVDSB4_P
LVDSB5_N: J29.E16 ; port LVDSB5_N
LVDSB5_P: J29.E15 ; port LVDSB5_P
LVDSB6_N: J29.J16 ; port LVDSB6_N
LVDSB6_P: J29.J15 ; port LVDSB6_P
LVDSB7_N: J29.K11 ; port LVDSB7_N
LVDSB7_P: J29.K10 ; port LVDSB7_P
LVDSB8_N: J29.F11 ; port LVDSB8_N
LVDSB8_P: J29.F10 ; port LVDSB8_P
LVDSB9_N: J29.F8 ; port LVDSB9_N
LVDSB9_P: J29.F7 ; port LVDSB9_P
LVDSB10_N: J29.F14 ; port LVDSB10_N
LVDSB10_P: J29.F13 ; port LVDSB10_P
LVDSB11_N: J29.K8 ; port LVDSB11_N
LVDSB11_P: J29.K7 ; port LVDSB11_P
LVDSB12_N: J29.K14 ; port LVDSB12_N
LVDSB12_P: J29.K13 ; port LVDSB12_P
LVDSB13_N: J29.J10 ; port LVDSB13_N
LVDSB13_P: J29.J9 ; port LVDSB13_P
LVDSB14_N: J29.J7 ; port LVDSB14_N
LVDSB14_P: J29.J6 ; port LVDSB14_P
LVDSB15_N: J29.J12 ; port LVDSB15_N
LVDSB15_P: J29.J13 ; port LVDSB15_P
MGTREFCLK0_FMC_N: J29.D5 ; port MGTREFCLK0_FMC_N
MGTREFCLK0_FMC_P: J29.D4 ; port MGTREFCLK0_FMC_P
MGTREFCLK1_FMC_N: J29.B21 ; port MGTREFCLK1_FMC_N
MGTREFCLK1_FMC_P: J29.B20 ; port MGTREFCLK1_FMC_P
PDN_ADC_FMC_VADJ: R218.1 ; port PDN_ADC_FMC_VADJ
PG-FPGA: D1.1(A) J29.D1 R85.1 R199.2
PG-M2C: D2.1(A) R199.1 ; port PG-M2C
RSTb_ADC_FMC_VADJ: R217.1 ; port RSTb_ADC_FMC_VADJ
SCL_FMC: J29.C30 ; port SCL_FMC
SCLK_FMC_VADJ: J29.G12 ; port SCLK_FMC_VADJ
SCLK_FPGA_VADJ: J29.C10 ; port SCLK_FPGA_VADJ
SDA_FMC: J29.C31 ; port SDA_FMC
SDI_FMC_VADJ: J29.G13 ; port SDI_FMC_VADJ
SDIOr_FPGA_VADJ: J29.C14 ; port SDIOr_FPGA_VADJ
SDIOw_FPGA_VADJ: J29.C11 ; port SDIOw_FPGA_VADJ
SDO_FMC_VADJ: J29.G15 ; port SDO_FMC_VADJ
SEN_ADC_FMC_VADJ: J29.G18 ; port SEN_ADC_FMC_VADJ
SEN_FPGA_VADJ: J29.C15 ; port SEN_FPGA_VADJ
TDI_FMC: J29.D30 R84.2
TDO_FMC: J29.D31 R84.1
NetD1_2: D1.2(K) R83.2
NetD2_2: D2.2(K) R87.2
NetJ29_F1: J29.F1 R85.2
NetJ29_H13: J29.H13 R217.2
NetJ29_H14: J29.H14 R218.2
NetJ29_H16: J29.H16 R200.2
NetR182_2: R182.2 R201.1

Not connected (* = marked no-connect by the designer): J29 A22* A23* A26* A27* A30* A31* A34* A35* A38* A39* B1* B4* B5* B8* B9* B24* B25* B28* B29* B32* B33* B36* B37* B40* C2* C3* C18* C19* C35* C37* C39* D11* D12* D14* D15* D17* D18* D29* D33* D34* D36* D38* D40* E18* E19* E21* E22* E24* E25* E27* E28* E30* E31* E33* E34* E36* E37* F19* F20* F22* F23* F25* F26* F28* F29* F31* F32* F34* F35* F37* F38* G19* H1* H4* H5* H7* H8* H10* H11* J2* J3* J24* J25* J27* J28* J30* J31* J33* J34* J36* J37* J39* K1* K4* K5* K25* K26* K28* K29* K31* K32* K34* K35* K37* K38* K40*

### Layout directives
differential pair; net class LVDS_A: LVDS12A_N, LVDS12A_P

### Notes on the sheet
- FPGA as SPI
  Peripheral
- (near R201) Shared pad
- (near R183) Shared pad

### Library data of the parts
D1 D2 = cmp00247: LED GREEN CLEAR CHIP SMD; Manufacturer: Lite-On Inc.; Current Rating (Amps): 20mA; Voltage - Forward (Vf) (Typ): 3.2V; SizeX_mm: 1.6; SizeY_mm: 0.8; SizeZ_mm: 0.65
J29 = VITA Male FMC: FMC, High Density Array, Male; Manufacturer: Samtec; UniqueID: cmp00010; Pitch (mm): 1.27
R83 = RSMD040202043: RES 3.9K OHM 5% 1/10W 0402; Manufacturer: Panasonic Electronic Components; CompType: Resistor SMD; Power (Watts): 0.1W, 1/10W; Temperature Coefficient: ±200ppm/°C; SizeX_mm: 1; SizeY_mm: 0.5; SizeZ_mm: 0.4
R84 R182-R184 R200 R201 R217 R218 = RSMD020101699: RES SMD 0 OHM JUMPER 1/20W 0201; Manufacturer: Panasonic Electronic Components; CompType: Resistor SMD; Power (Watts): 0.05W, 1/20W
R85 R86 R199 = RSMD020100147: RES SMD 220 OHM 1% 1/20W 0201; Manufacturer: Panasonic Electronic Components; CompType: Resistor SMD; Power (Watts): 0.05W, 1/20W; Temperature Coefficient: ±200ppm/°C
R87 = RSMD040200007: RES SMD 1K OHM 1% 1/5W 0402; Manufacturer: Panasonic Electronic Components; CompType: Resistor SMD; Power (Watts): 0.2W, 1/5W; Temperature Coefficient: ±100ppm/°C; SizeX_mm: 1; SizeY_mm: 0.5; SizeZ_mm: 0.4

## Sheet ADC34RF7x_USB_RevA.SchDoc: USB Interface
size 431 x 279 mm; Date: Not shown in title block; ApprovedBy: Not shown in title block; CheckedBy: Not shown in title block; Author: Not shown in title block; CompanyName: Not shown in title block; DrawnBy: CW; Engineer: Not shown in title block; Organization: Not shown in title block; Address1: Not shown in title block; Address2: Not shown in title block; Address3: Not shown in title block; Address4: Not shown in title block; DocumentNumber: 11; Revision: Use project parameter SCH_Rev; SheetNumber: 8; SheetTotal: 19; PageSetup: Record=PageOptions¦CenterHorizontal=True¦CenterVertical=True¦PrintScale=1.00¦XCorrection=1.00¦YCorrection=1.00¦PrintKind=0¦BorderSize=5000000¦LeftOffset=0¦BottomOffset=0¦Orientation=2¦PaperLength=1000¦PaperWidth=1000¦Scale=100¦PaperSource=15¦PrintQuality=600¦MediaType=1¦DitherType=10¦PaperKind=Letter¦PrintScaleMode=1
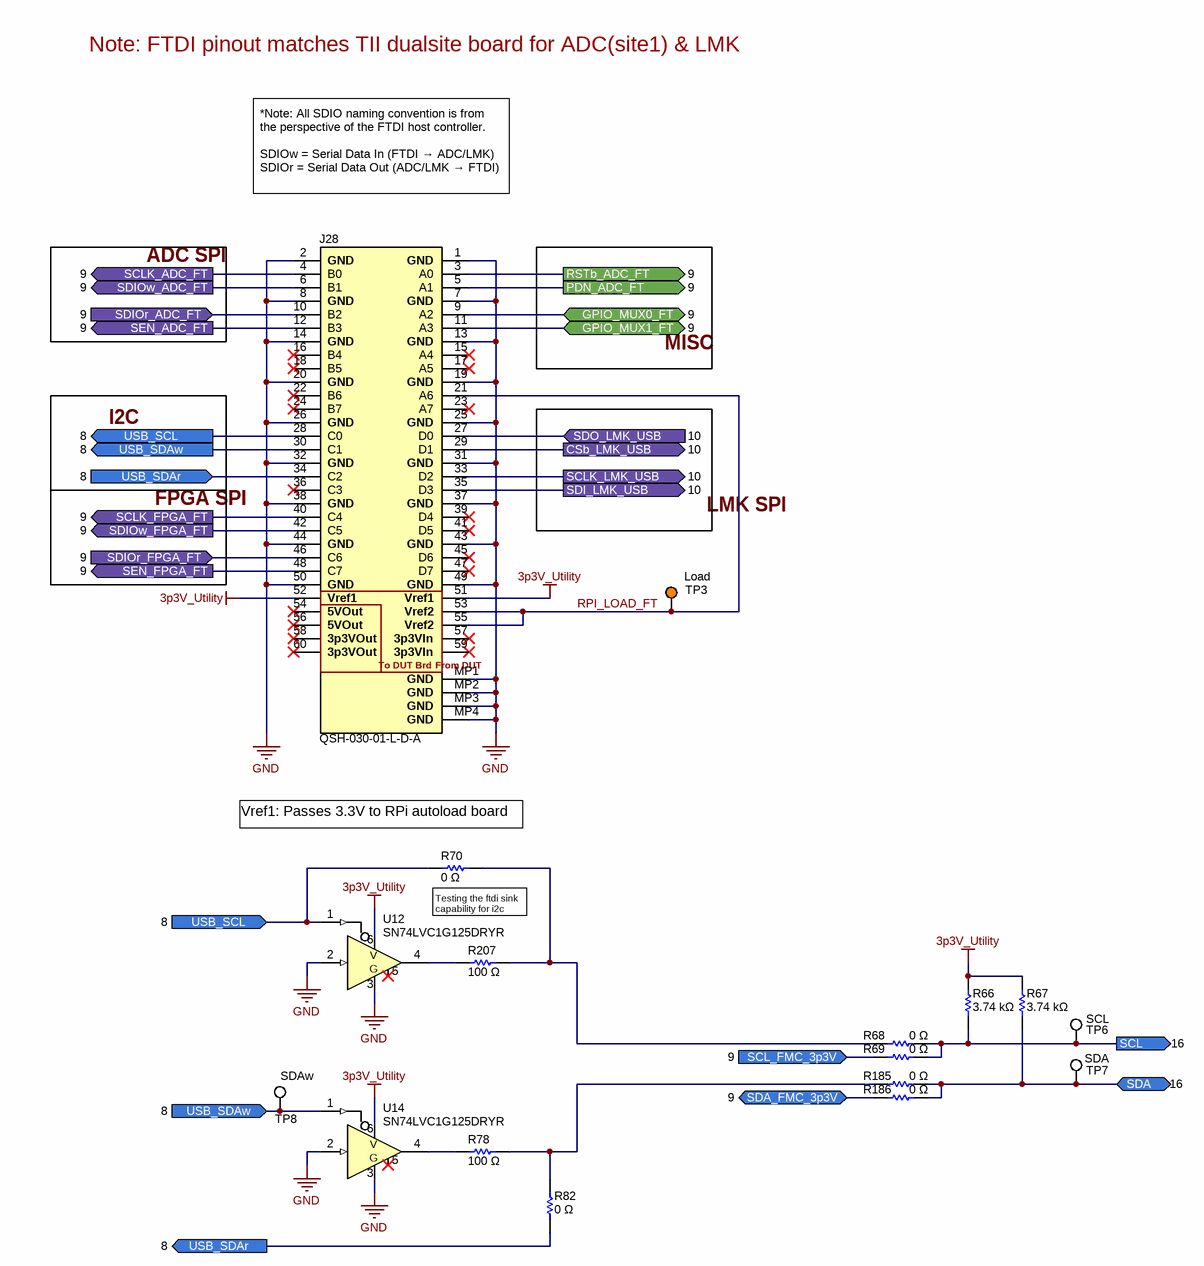
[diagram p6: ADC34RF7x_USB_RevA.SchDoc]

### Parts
J28  QSH-030-01-L-D-A  [FTDI_Dongle_003]
R66  value 3.74 kΩ  [0201]  (hidden comment: ERJ-1GNF3741C)
R67  value 3.74 kΩ  [0201]  (hidden comment: ERJ-1GNF3741C)
R68  value 0 Ω  [0201]  (hidden comment: ERJ-1GN0R00C)
R69  value 0 Ω  [0201]  (hidden comment: ERJ-1GN0R00C)
R70  value 0 Ω  [0201]  (hidden comment: ERJ-1GN0R00C)
R78  value 100 Ω  [0201]  (hidden comment: ERJ-1GNF1000C)
R82  value 0 Ω  [0201]  (hidden comment: ERJ-1GN0R00C)
R185  value 0 Ω  [0201]  (hidden comment: ERJ-1GN0R00C)
R186  value 0 Ω  [0201]  (hidden comment: ERJ-1GN0R00C)
R207  value 100 Ω  [0201]  (hidden comment: ERJ-1GNF1000C)
TP3  Text1: Load  [Keystone5003]  (hidden comment: 5003)
TP6  Text1: SCL  [Keystone5002]  (hidden comment: 5002)
TP7  Text1: SDA  [Keystone5002]  (hidden comment: 5002)
TP8  Text1: SDAw  [Keystone5002]  (hidden comment: 5002)
U12  SN74LVC1G125DRYR  [DRY0006A]
U14  SN74LVC1G125DRYR  [DRY0006A]

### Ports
CSb_LMK_USB (out, see 10), GPIO_MUX0_FT (bidir, see 9), GPIO_MUX1_FT (bidir, see 9), PDN_ADC_FT (out, see 9), RSTb_ADC_FT (out, see 9), SCL (out, see 16), SCL_FMC_3p3V (in, see 9), SCLK_ADC_FT (out, see 9), SCLK_FPGA_FT (out, see 9), SCLK_LMK_USB (out, see 10), SDA (bidir, see 16), SDA_FMC_3p3V (bidir, see 9), SDI_LMK_USB (out, see 10), SDIOr_ADC_FT (in, see 9), SDIOr_FPGA_FT (in, see 9), SDIOw_ADC_FT (out, see 9), SDIOw_FPGA_FT (out, see 9), SDO_LMK_USB (in, see 10), SEN_ADC_FT (out, see 9), SEN_FPGA_FT (out, see 9), USB_SCL (in, see 8), USB_SCL (out, see 8), USB_SDAr (in, see 8), USB_SDAr (out, see 8), USB_SDAw (in, see 8), USB_SDAw (out, see 8)

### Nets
3p3V_Utility: J28.51(Vref1) J28.52(Vref1) R66.2 R67.2 U12.6(VCC) U14.6(VCC)
GND: J28.1(GND) J28.2(GND) J28.7(GND) J28.8(GND) J28.13(GND) J28.14(GND) J28.19(GND) J28.20(GND) J28.25(GND) J28.26(GND) J28.31(GND) J28.32(GND) J28.37(GND) J28.38(GND) J28.43(GND) J28.44(GND) J28.49(GND) J28.50(GND) J28.MP1(GND) J28.MP2(GND) J28.MP3(GND) J28.MP4(GND) U12.2(A) U12.3(GND) U14.2(A) U14.3(GND)
CSb_LMK_USB: J28.29(D1) ; port CSb_LMK_USB
GPIO_MUX0_FT: J28.9(A2) ; port GPIO_MUX0_FT
GPIO_MUX1_FT: J28.11(A3) ; port GPIO_MUX1_FT
PDN_ADC_FT: J28.5(A1) ; port PDN_ADC_FT
RPI_LOAD_FT: J28.21(A6) J28.53(Vref2) J28.55(Vref2) TP3.1
RSTb_ADC_FT: J28.3(A0) ; port RSTb_ADC_FT
SCL: R66.1 R68.1 R69.1 TP6.1 ; port SCL
SCL_FMC_3p3V: R69.2 ; port SCL_FMC_3p3V
SCLK_ADC_FT: J28.4(B0) ; port SCLK_ADC_FT
SCLK_FPGA_FT: J28.40(C4) ; port SCLK_FPGA_FT
SCLK_LMK_USB: J28.33(D2) ; port SCLK_LMK_USB
SDA: R67.1 R185.1 R186.1 TP7.1 ; port SDA
SDA_FMC_3p3V: R186.2 ; port SDA_FMC_3p3V
SDI_LMK_USB: J28.35(D3) ; port SDI_LMK_USB
SDIOr_ADC_FT: J28.10(B2) ; port SDIOr_ADC_FT
SDIOr_FPGA_FT: J28.46(C6) ; port SDIOr_FPGA_FT
SDIOw_ADC_FT: J28.6(B1) ; port SDIOw_ADC_FT
SDIOw_FPGA_FT: J28.42(C5) ; port SDIOw_FPGA_FT
SDO_LMK_USB: J28.27(D0) ; port SDO_LMK_USB
SEN_ADC_FT: J28.12(B3) ; port SEN_ADC_FT
SEN_FPGA_FT: J28.48(C7) ; port SEN_FPGA_FT
USB_SCL: J28.28(C0) R70.1 U12.1(~{OE}) ; port USB_SCL
USB_SDAr: J28.34(C2) R82.1 ; port USB_SDAr
USB_SDAw: J28.30(C1) TP8.1 U14.1(~{OE}) ; port USB_SDAw
NetR68_2: R68.2 R70.2 R207.2
NetR78_1: R78.1 U14.4(Y)
NetR78_2: R78.2 R82.2 R185.2
NetR207_1: R207.1 U12.4(Y)

Not connected (* = marked no-connect by the designer): J28 15(A4)* 16(B4)* 17(A5)* 18(B5)* 22(B6)* 23(A7)* 24(B7)* 36(C3)* 39(D4)* 41(D5)* 45(D6)* 47(D7)* 54(5VOut)* 56(5VOut)* 57(3p3VIn)* 58(3p3VOut)* 59(3p3VIn)* 60(3p3VOut)*; U12 5(NC)*; U14 5(NC)*

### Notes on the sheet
- Note: FTDI pinout matches TII dualsite board for ADC(site1) & LMK
- *Note: All SDIO naming convention is from the perspective of the FTDI host controller.
  SDIOw = Serial Data In (FTDI → ADC/LMK)
  SDIOr = Serial Data Out (ADC/LMK → FTDI)
- ADC SPI
- MISC
- I2C
- FPGA SPI
- LMK SPI
- (near R70) Vref1: Passes 3.3V to RPi autoload board
- Testing the ftdi sink capability for i2c

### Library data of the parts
J28 = cmp00061: FTDI Dongle EVM Mating connector and standoff holes; Manufacturer: Samtec
R66 R67 = RSMD020100617: RES SMD 3.74K OHM 1% 1/20W 0201; Manufacturer: Panasonic Electronic Components; CompType: Resistor SMD; Power (Watts): 0.05W, 1/20W; Temperature Coefficient: ±200ppm/°C
R68-R70 R82 R185 R186 = RSMD020101699: as R84 on sheet ADC34RF7x_FMC_RevA
R78 R207 = RSMD020100289: RES SMD 100 OHM 1% 1/20W 0201; Manufacturer: Panasonic Electronic Components; CompType: Resistor SMD; Power (Watts): 0.05W, 1/20W; Temperature Coefficient: ±200ppm/°C
TP3 = cmp00053: Test Point, Miniature, Orange, TH; Manufacturer: Keystone
TP6-TP8 = cmp00052: Test Point, Miniature, White, TH; Manufacturer: Keystone
U12 U14 = cmp00343: Low-Power Single Bus Buffer Gate With 3-State Output; Manufacturer: Texas Instruments; Alt PartNumber: SN74LVC1G125DRYT

## Sheet ADC34RF7x_LVL_Shft_RevA.SchDoc: Level Shifting
size 431 x 279 mm; Date: Not shown in title block; ApprovedBy: Not shown in title block; CheckedBy: Not shown in title block; Author: Not shown in title block; CompanyName: Not shown in title block; DrawnBy: CW; Engineer: Not shown in title block; Organization: Not shown in title block; Address1: Not shown in title block; Address2: Not shown in title block; Address3: Not shown in title block; Address4: Not shown in title block; DocumentNumber: 10; Revision: Use project parameter SCH_Rev; SheetNumber: 9; SheetTotal: 19; PageSetup: Record=PageOptions¦CenterHorizontal=True¦CenterVertical=True¦PrintScale=1.00¦XCorrection=1.00¦YCorrection=1.00¦PrintKind=0¦BorderSize=5000000¦LeftOffset=0¦BottomOffset=0¦Orientation=2¦PaperLength=1000¦PaperWidth=1000¦Scale=100¦PaperSource=15¦PrintQuality=600¦MediaType=1¦DitherType=10¦PaperKind=Letter¦PrintScaleMode=1
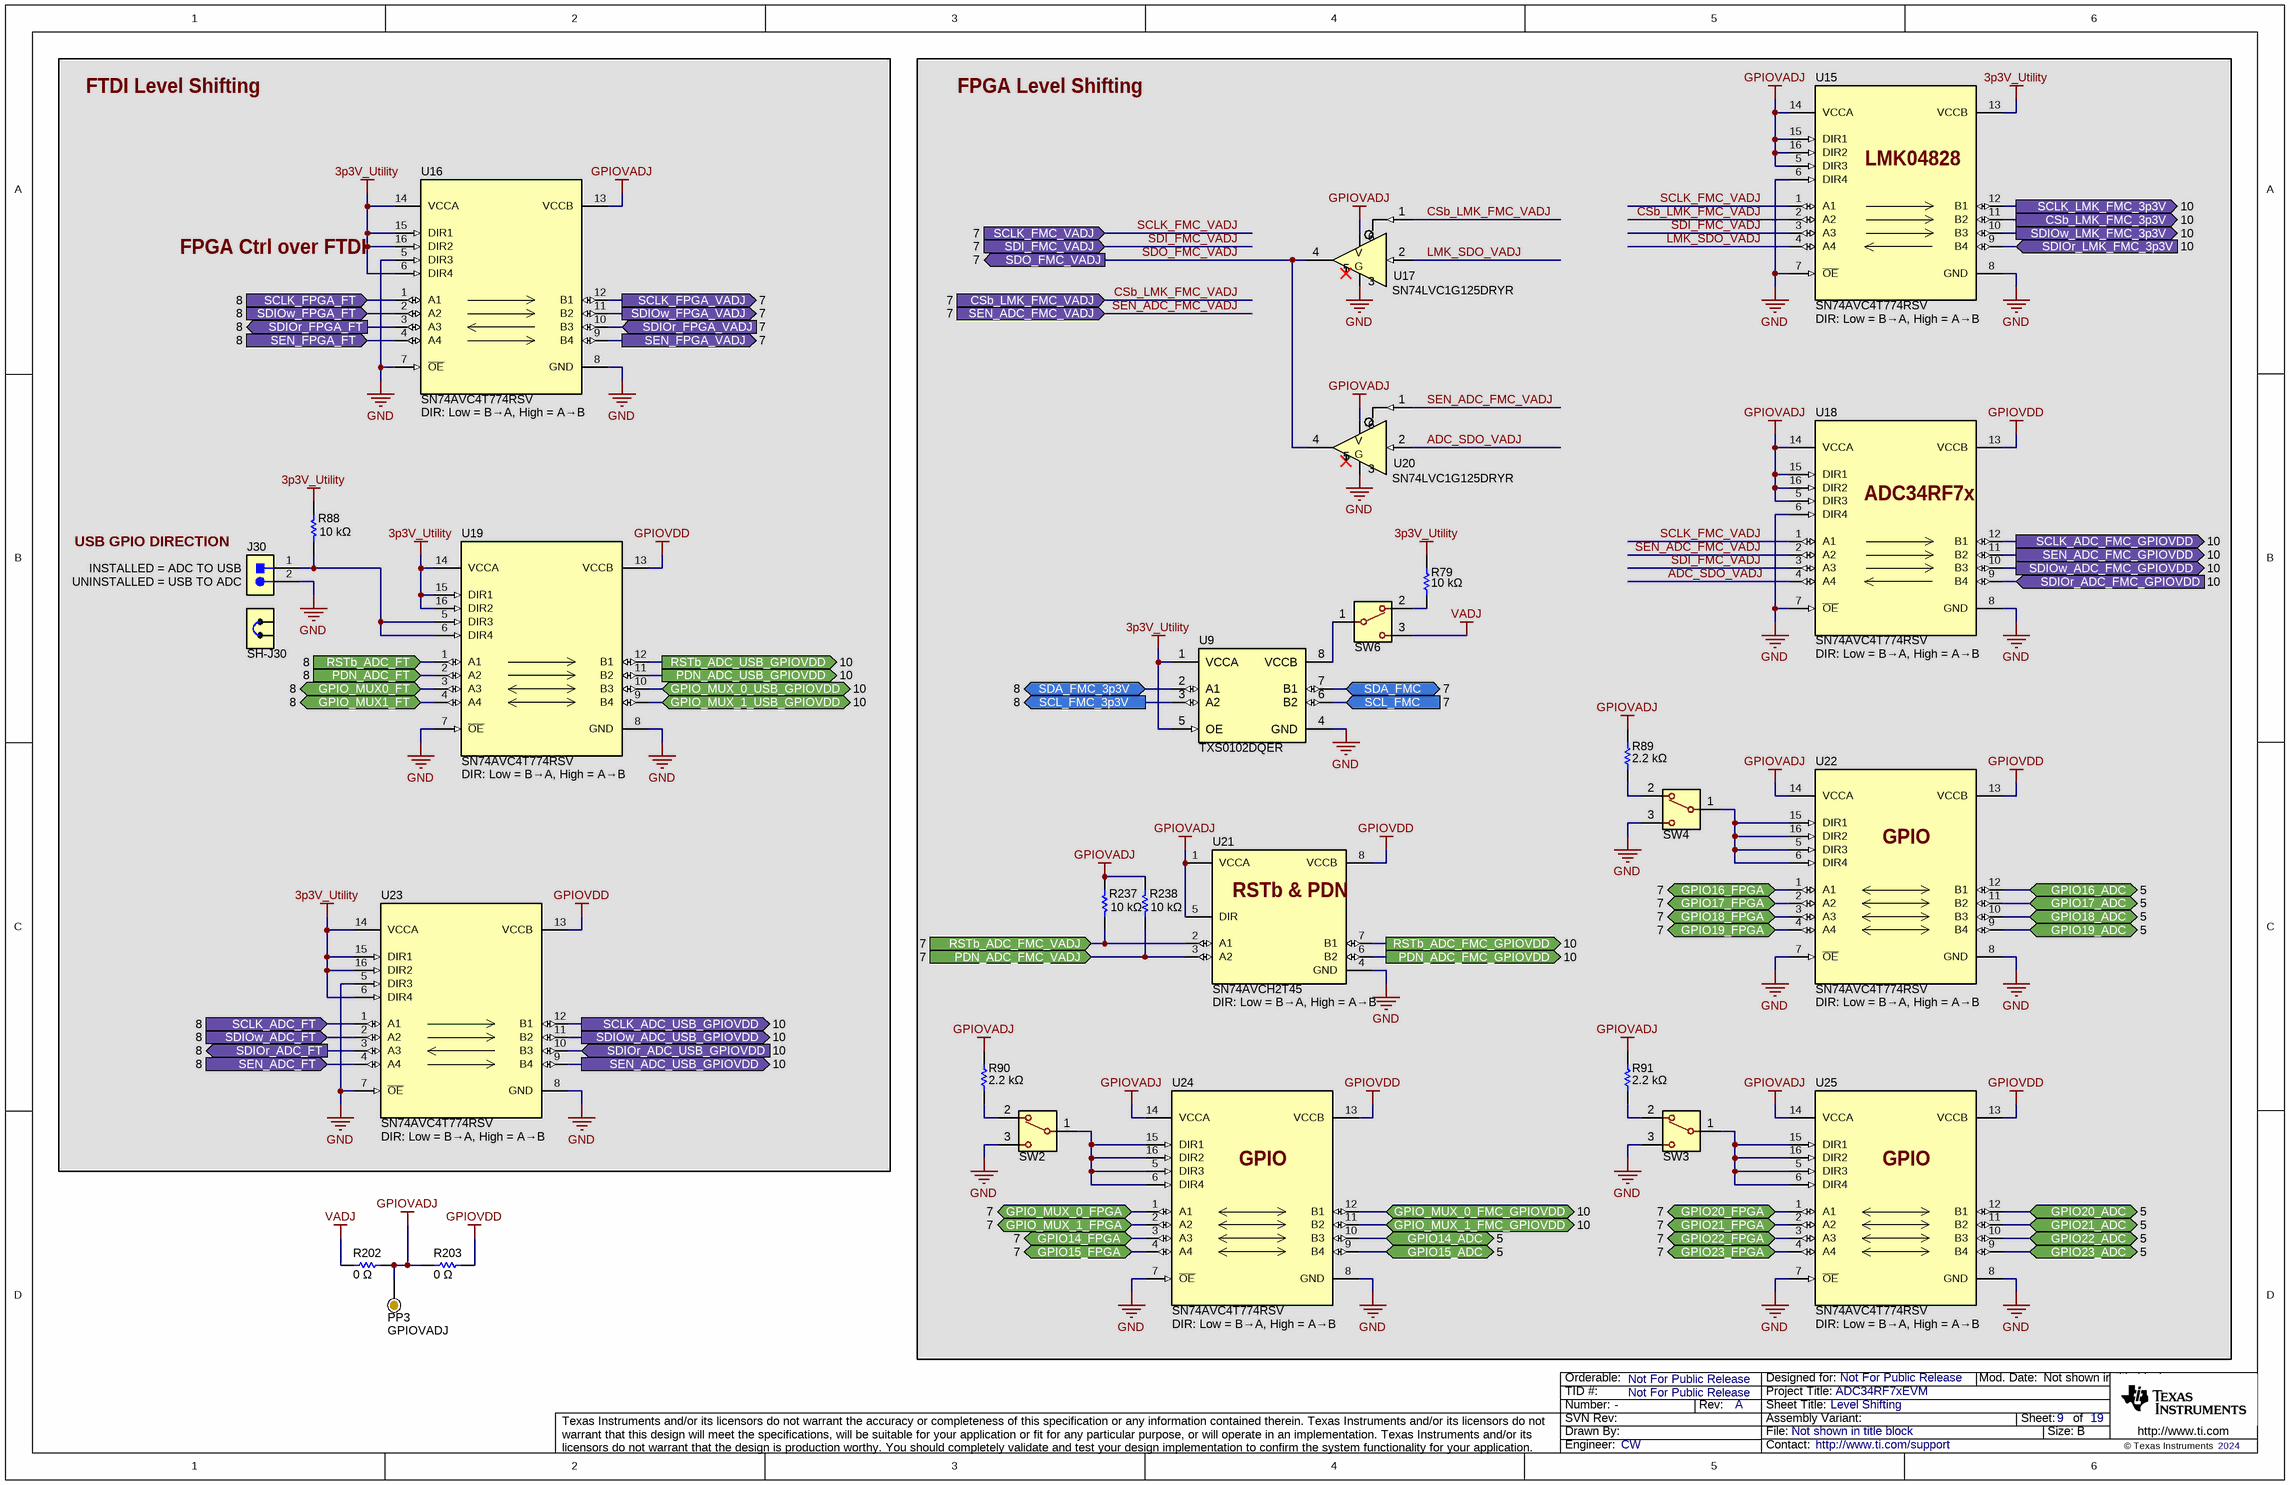
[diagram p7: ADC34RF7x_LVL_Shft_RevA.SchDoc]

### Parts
J30  GRPB021VWVN-RC  [PBC02SAAN]  (value not drawn)
PP3  Text1: GPIOVADJ  [ProbePoint_TH_40mil]  (hidden comment: Probe Point)  (no BOM)
R79  value 10 kΩ  [0201]  (hidden comment: ERJ-1GNF1002C)
R88  value 10 kΩ  [0201]  (hidden comment: ERJ-1GNF1002C)
R89  value 2.2 kΩ  [0201]  (hidden comment: ERJ-1GNF2201C)
R90  value 2.2 kΩ  [0201]  (hidden comment: ERJ-1GNF2201C)
R91  value 2.2 kΩ  [0201]  (hidden comment: ERJ-1GNF2201C)
R202  value 0 Ω  [0603L]  (hidden comment: ERJ-U030R00V)
R203  value 0 Ω  [0603L]  (hidden comment: ERJ-U030R00V)
R237  value 10 kΩ  [0201]  (hidden comment: ERJ-1GNF1002C)
R238  value 10 kΩ  [0201]  (hidden comment: ERJ-1GNF1002C)
SH-J30  SPC02SYAN  [SPC02SYAN]  (value not drawn)
SW2  450301014042  [450301014042]  (value not drawn)
SW3  450301014042  [450301014042]  (value not drawn)
SW4  450301014042  [450301014042]  (value not drawn)
SW6  450301014042  [450301014042]  (value not drawn)
U9  TXS0102DQER  [DQE0008A]
U15  SN74AVC4T774RSV  Text1: DIR: Low = B→A, High = A→B  [RSV0016A]
U16  SN74AVC4T774RSV  Text1: DIR: Low = B→A, High = A→B  [RSV0016A]
U17  SN74LVC1G125DRYR  [DRY0006A]
U18  SN74AVC4T774RSV  Text1: DIR: Low = B→A, High = A→B  [RSV0016A]
U19  SN74AVC4T774RSV  Text1: DIR: Low = B→A, High = A→B  [RSV0016A]
U20  SN74LVC1G125DRYR  [DRY0006A]
U21  SN74AVCH2T45  Text1: DIR: Low = B→A, High = A→B  [DCU0008A]
U22  SN74AVC4T774RSV  Text1: DIR: Low = B→A, High = A→B  [RSV0016A]
U23  SN74AVC4T774RSV  Text1: DIR: Low = B→A, High = A→B  [RSV0016A]
U24  SN74AVC4T774RSV  Text1: DIR: Low = B→A, High = A→B  [RSV0016A]
U25  SN74AVC4T774RSV  Text1: DIR: Low = B→A, High = A→B  [RSV0016A]

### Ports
CSb_LMK_FMC_3p3V (out, see 10), CSb_LMK_FMC_VADJ (in, see 7), GPIO14_ADC (bidir, see 5), GPIO14_FPGA (bidir, see 7), GPIO15_ADC (bidir, see 5), GPIO15_FPGA (bidir, see 7), GPIO16_ADC (bidir, see 5), GPIO16_FPGA (bidir, see 7), GPIO17_ADC (bidir, see 5), GPIO17_FPGA (bidir, see 7), GPIO18_ADC (bidir, see 5), GPIO18_FPGA (bidir, see 7), GPIO19_ADC (bidir, see 5), GPIO19_FPGA (bidir, see 7), GPIO20_ADC (bidir, see 5), GPIO20_FPGA (bidir, see 7), GPIO21_ADC (bidir, see 5), GPIO21_FPGA (bidir, see 7), GPIO22_ADC (bidir, see 5), GPIO22_FPGA (bidir, see 7), GPIO23_ADC (bidir, see 5), GPIO23_FPGA (bidir, see 7), GPIO_MUX0_FT (bidir, see 8), GPIO_MUX1_FT (bidir, see 8), GPIO_MUX_0_FMC_GPIOVDD (bidir, see 10), GPIO_MUX_0_FPGA (bidir, see 7), GPIO_MUX_0_USB_GPIOVDD (bidir, see 10), GPIO_MUX_1_FMC_GPIOVDD (bidir, see 10), GPIO_MUX_1_FPGA (bidir, see 7), GPIO_MUX_1_USB_GPIOVDD (bidir, see 10), PDN_ADC_FMC_GPIOVDD (out, see 10), PDN_ADC_FMC_VADJ (in, see 7), PDN_ADC_FT (in, see 8), PDN_ADC_USB_GPIOVDD (out, see 10), RSTb_ADC_FMC_GPIOVDD (out, see 10), RSTb_ADC_FMC_VADJ (in, see 7), RSTb_ADC_FT (in, see 8), RSTb_ADC_USB_GPIOVDD (out, see 10), SCL_FMC (in, see 7), SCL_FMC_3p3V (out, see 8), SCLK_ADC_FMC_GPIOVDD (out, see 10), SCLK_ADC_FT (in, see 8), SCLK_ADC_USB_GPIOVDD (out, see 10), SCLK_FMC_VADJ (in, see 7), SCLK_FPGA_FT (in, see 8), SCLK_FPGA_VADJ (out, see 7), SCLK_LMK_FMC_3p3V (out, see 10), SDA_FMC (bidir, see 7), SDA_FMC_3p3V (bidir, see 8), SDI_FMC_VADJ (in, see 7), SDIOr_ADC_FMC_GPIOVDD (in, see 10), SDIOr_ADC_FT (out, see 8), SDIOr_ADC_USB_GPIOVDD (in, see 10), SDIOr_FPGA_FT (out, see 8), SDIOr_FPGA_VADJ (in, see 7), SDIOr_LMK_FMC_3p3V (in, see 10), SDIOw_ADC_FMC_GPIOVDD (out, see 10), SDIOw_ADC_FT (in, see 8), SDIOw_ADC_USB_GPIOVDD (out, see 10), SDIOw_FPGA_FT (in, see 8), SDIOw_FPGA_VADJ (out, see 7), SDIOw_LMK_FMC_3p3V (out, see 10), SDO_FMC_VADJ (out, see 7), SEN_ADC_FMC_GPIOVDD (out, see 10), SEN_ADC_FMC_VADJ (in, see 7), SEN_ADC_FT (in, see 8), SEN_ADC_USB_GPIOVDD (out, see 10), SEN_FPGA_FT (in, see 8), SEN_FPGA_VADJ (out, see 7)

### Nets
3p3V_Utility: R79.1 R88.2 U9.1(VCCA) U9.5(OE) U15.13(VCCB) U16.6(DIR4) U16.14(VCCA) U16.15(DIR1) U16.16(DIR2) U19.14(VCCA) U19.15(DIR1) U19.16(DIR2) U23.6(DIR4) U23.14(VCCA) U23.15(DIR1) U23.16(DIR2)
GND: J30.2 SW2.3 SW3.3 SW4.3 U9.4(GND) U15.6(DIR4) U15.7(~{OE}) U15.8(GND) U16.5(DIR3) U16.7(~{OE}) U16.8(GND) U17.3(GND) U18.6(DIR4) U18.7(~{OE}) U18.8(GND) U19.7(~{OE}) U19.8(GND) U20.3(GND) U21.4(GND) U22.7(~{OE}) U22.8(GND) U23.5(DIR3) U23.7(~{OE}) U23.8(GND) U24.7(~{OE}) U24.8(GND) U25.7(~{OE}) U25.8(GND)
GPIOVADJ: PP3.1 R89.2 R90.2 R91.2 R202.2 R203.1 R237.2 R238.2 U15.5(DIR3) U15.14(VCCA) U15.15(DIR1) U15.16(DIR2) U16.13(VCCB) U17.6(VCC) U18.5(DIR3) U18.14(VCCA) U18.15(DIR1) U18.16(DIR2) U20.6(VCC) U21.1(VCCA) U21.5(DIR) U22.14(VCCA) U24.14(VCCA) U25.14(VCCA)
GPIOVDD: R203.2 U18.13(VCCB) U19.13(VCCB) U21.8(VCCB) U22.13(VCCB) U23.13(VCCB) U24.13(VCCB) U25.13(VCCB)
VADJ: R202.1 SW6.3
ADC_SDO_VADJ: U18.4(A4) U20.2(A)
CSb_LMK_FMC_3p3V: U15.11(B2) ; port CSb_LMK_FMC_3p3V
CSb_LMK_FMC_VADJ: U15.2(A2) U17.1(~{OE}) ; port CSb_LMK_FMC_VADJ
GPIO14_ADC: U24.10(B3) ; port GPIO14_ADC
GPIO14_FPGA: U24.3(A3) ; port GPIO14_FPGA
GPIO15_ADC: U24.9(B4) ; port GPIO15_ADC
GPIO15_FPGA: U24.4(A4) ; port GPIO15_FPGA
GPIO16_ADC: U22.12(B1) ; port GPIO16_ADC
GPIO16_FPGA: U22.1(A1) ; port GPIO16_FPGA
GPIO17_ADC: U22.11(B2) ; port GPIO17_ADC
GPIO17_FPGA: U22.2(A2) ; port GPIO17_FPGA
GPIO18_ADC: U22.10(B3) ; port GPIO18_ADC
GPIO18_FPGA: U22.3(A3) ; port GPIO18_FPGA
GPIO19_ADC: U22.9(B4) ; port GPIO19_ADC
GPIO19_FPGA: U22.4(A4) ; port GPIO19_FPGA
GPIO20_ADC: U25.12(B1) ; port GPIO20_ADC
GPIO20_FPGA: U25.1(A1) ; port GPIO20_FPGA
GPIO21_ADC: U25.11(B2) ; port GPIO21_ADC
GPIO21_FPGA: U25.2(A2) ; port GPIO21_FPGA
GPIO22_ADC: U25.10(B3) ; port GPIO22_ADC
GPIO22_FPGA: U25.3(A3) ; port GPIO22_FPGA
GPIO23_ADC: U25.9(B4) ; port GPIO23_ADC
GPIO23_FPGA: U25.4(A4) ; port GPIO23_FPGA
GPIO_MUX0_FT: U19.3(A3) ; port GPIO_MUX0_FT
GPIO_MUX1_FT: U19.4(A4) ; port GPIO_MUX1_FT
GPIO_MUX_0_FMC_GPIOVDD: U24.12(B1) ; port GPIO_MUX_0_FMC_GPIOVDD
GPIO_MUX_0_FPGA: U24.1(A1) ; port GPIO_MUX_0_FPGA
GPIO_MUX_0_USB_GPIOVDD: U19.10(B3) ; port GPIO_MUX_0_USB_GPIOVDD
GPIO_MUX_1_FMC_GPIOVDD: U24.11(B2) ; port GPIO_MUX_1_FMC_GPIOVDD
GPIO_MUX_1_FPGA: U24.2(A2) ; port GPIO_MUX_1_FPGA
GPIO_MUX_1_USB_GPIOVDD: U19.9(B4) ; port GPIO_MUX_1_USB_GPIOVDD
LMK_SDO_VADJ: U15.4(A4) U17.2(A)
PDN_ADC_FMC_GPIOVDD: U21.6(B2) ; port PDN_ADC_FMC_GPIOVDD
PDN_ADC_FMC_VADJ: R238.1 U21.3(A2) ; port PDN_ADC_FMC_VADJ
PDN_ADC_FT: U19.2(A2) ; port PDN_ADC_FT
PDN_ADC_USB_GPIOVDD: U19.11(B2) ; port PDN_ADC_USB_GPIOVDD
RSTb_ADC_FMC_GPIOVDD: U21.7(B1) ; port RSTb_ADC_FMC_GPIOVDD
RSTb_ADC_FMC_VADJ: R237.1 U21.2(A1) ; port RSTb_ADC_FMC_VADJ
RSTb_ADC_FT: U19.1(A1) ; port RSTb_ADC_FT
RSTb_ADC_USB_GPIOVDD: U19.12(B1) ; port RSTb_ADC_USB_GPIOVDD
SCL_FMC: U9.6(B2) ; port SCL_FMC
SCL_FMC_3p3V: U9.3(A2) ; port SCL_FMC_3p3V
SCLK_ADC_FMC_GPIOVDD: U18.12(B1) ; port SCLK_ADC_FMC_GPIOVDD
SCLK_ADC_FT: U23.1(A1) ; port SCLK_ADC_FT
SCLK_ADC_USB_GPIOVDD: U23.12(B1) ; port SCLK_ADC_USB_GPIOVDD
SCLK_FMC_VADJ: U15.1(A1) U18.1(A1) ; port SCLK_FMC_VADJ
SCLK_FPGA_FT: U16.1(A1) ; port SCLK_FPGA_FT
SCLK_FPGA_VADJ: U16.12(B1) ; port SCLK_FPGA_VADJ
SCLK_LMK_FMC_3p3V: U15.12(B1) ; port SCLK_LMK_FMC_3p3V
SDA_FMC: U9.7(B1) ; port SDA_FMC
SDA_FMC_3p3V: U9.2(A1) ; port SDA_FMC_3p3V
SDI_FMC_VADJ: U15.3(A3) U18.3(A3) ; port SDI_FMC_VADJ
SDIOr_ADC_FMC_GPIOVDD: U18.9(B4) ; port SDIOr_ADC_FMC_GPIOVDD
SDIOr_ADC_FT: U23.3(A3) ; port SDIOr_ADC_FT
SDIOr_ADC_USB_GPIOVDD: U23.10(B3) ; port SDIOr_ADC_USB_GPIOVDD
SDIOr_FPGA_FT: U16.3(A3) ; port SDIOr_FPGA_FT
SDIOr_FPGA_VADJ: U16.10(B3) ; port SDIOr_FPGA_VADJ
SDIOr_LMK_FMC_3p3V: U15.9(B4) ; port SDIOr_LMK_FMC_3p3V
SDIOw_ADC_FMC_GPIOVDD: U18.10(B3) ; port SDIOw_ADC_FMC_GPIOVDD
SDIOw_ADC_FT: U23.2(A2) ; port SDIOw_ADC_FT
SDIOw_ADC_USB_GPIOVDD: U23.11(B2) ; port SDIOw_ADC_USB_GPIOVDD
SDIOw_FPGA_FT: U16.2(A2) ; port SDIOw_FPGA_FT
SDIOw_FPGA_VADJ: U16.11(B2) ; port SDIOw_FPGA_VADJ
SDIOw_LMK_FMC_3p3V: U15.10(B3) ; port SDIOw_LMK_FMC_3p3V
SDO_FMC_VADJ: U17.4(Y) U20.4(Y) ; port SDO_FMC_VADJ
SEN_ADC_FMC_GPIOVDD: U18.11(B2) ; port SEN_ADC_FMC_GPIOVDD
SEN_ADC_FMC_VADJ: U18.2(A2) U20.1(~{OE}) ; port SEN_ADC_FMC_VADJ
SEN_ADC_FT: U23.4(A4) ; port SEN_ADC_FT
SEN_ADC_USB_GPIOVDD: U23.9(B4) ; port SEN_ADC_USB_GPIOVDD
SEN_FPGA_FT: U16.4(A4) ; port SEN_FPGA_FT
SEN_FPGA_VADJ: U16.9(B4) ; port SEN_FPGA_VADJ
NetJ30_1: J30.1 R88.1 U19.5(DIR3) U19.6(DIR4)
NetR79_2: R79.2 SW6.2(COMM)
NetR89_1: R89.1 SW4.2(COMM)
NetR90_1: R90.1 SW2.2(COMM)
NetR91_1: R91.1 SW3.2(COMM)
NetSW2_1: SW2.1 U24.5(DIR3) U24.6(DIR4) U24.15(DIR1) U24.16(DIR2)
NetSW3_1: SW3.1 U25.5(DIR3) U25.6(DIR4) U25.15(DIR1) U25.16(DIR2)
NetSW4_1: SW4.1 U22.5(DIR3) U22.6(DIR4) U22.15(DIR1) U22.16(DIR2)
NetSW6_1: SW6.1 U9.8(VCCB)

Not connected (* = marked no-connect by the designer): U17 5(NC)*; U20 5(NC)*

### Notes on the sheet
- FTDI Level Shifting
- FPGA Level Shifting
- (near U15) LMK04828
- (near U16) FPGA Ctrl over FTDI
- (near U18) ADC34RF7x
- USB GPIO DIRECTION
- (near J30) INSTALLED = ADC TO USB
- UNINSTALLED = USB TO ADC
- (near U22) GPIO
- (near U21) RSTb & PDN
- (near U24) GPIO
- (near U25) GPIO

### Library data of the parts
J30 = TSW-102-14-L-S: as J19 on sheet ADC34RF7x_ADC_Power_RevA
PP3 = Probe Point: Probe Point that can be used in lue of a test point; UniqueID: cmp00025
R79 R88 R237 R238 = RSMD020100762: RES SMD 10K OHM 1% 1/20W 0201; Manufacturer: Panasonic Electronic Components; CompType: Resistor SMD; Power (Watts): 0.05W, 1/20W; Temperature Coefficient: ±200ppm/°C
R89-R91 = RSMD020100606: RES SMD 2.2K OHM 1% 1/20W 0201; Manufacturer: Panasonic Electronic Components; CompType: Resistor SMD; Power (Watts): 0.05W, 1/20W; Temperature Coefficient: ±200ppm/°C
R202 R203 = RSMD060312253: RES 0 OHM JUMPER 0603 SMD; Manufacturer: Panasonic Electronic Components; CompType: Resistor SMD; Power (Watts): 0.1W, 1/10W; Temperature Coefficient: ±200ppm/°C; SizeX_mm: 1.6; SizeY_mm: 0.8; SizeZ_mm: 0.55
SH-J30 = cmp00093: as SH-J19 on sheet ADC34RF7x_ADC_Power_RevA
SW2-SW4 SW6 = cmp00353: Switch Slide SPDT 12V, 500mA; Manufacturer: Wurth Elektronik; Text2: TO ADC; Text3: FROM ADC
U9 = TXS0102DQER: 2-BIT BIDIRECTIONAL VOLTAGE-LEVEL TRANSLATOR, DQE0008A (X2SON-8). Open drain friendly; Alternate Manufacturer: Texas Instruments; Green_Lifecycle: Active; SizeAreaWB_mm2: 6.16; Green_REACh: Passed; SizeZ_mm: 0.4; SizeX_mm: 1; SizeY_mm: 1.4; CompType: IC; AEC Qualified: N
U15 U16 U18 U19 U22-U25 = cmp00171: Translation - Voltage Levels 4-bit dual-supply bus transceiver with 3-state outputs and independent direction control inputs; Manufacturer: Texas Instruments; Alt PartNumber: SN74AXC4T774RSV; CompType: Level Shifter
U17 U20 = cmp00343: as U12 on sheet ADC34RF7x_USB_RevA
U21 = cmp00175: Dual-Bit Dual-Supply Bus Transceiver With Configurable Voltage Translation And 3-State Outputs; PartNumber: SN74AVCH2T45DCU; Manufacturer: Texas Instruments; Alt PartNumber: SN74AXCH2T45DCU; CompType: Level Shifter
